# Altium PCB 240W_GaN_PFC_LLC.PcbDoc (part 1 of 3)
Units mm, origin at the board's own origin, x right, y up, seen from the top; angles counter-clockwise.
Board outline 120 x 71.8 mm, 4 copper layers (Top Layer, Layer 1, Layer 2, Bottom Layer), stack 1.787 mm thick; 163 components, 87 nets, 528 pads, 288 vias.
Unrouted connection lines stored in the file: 3.
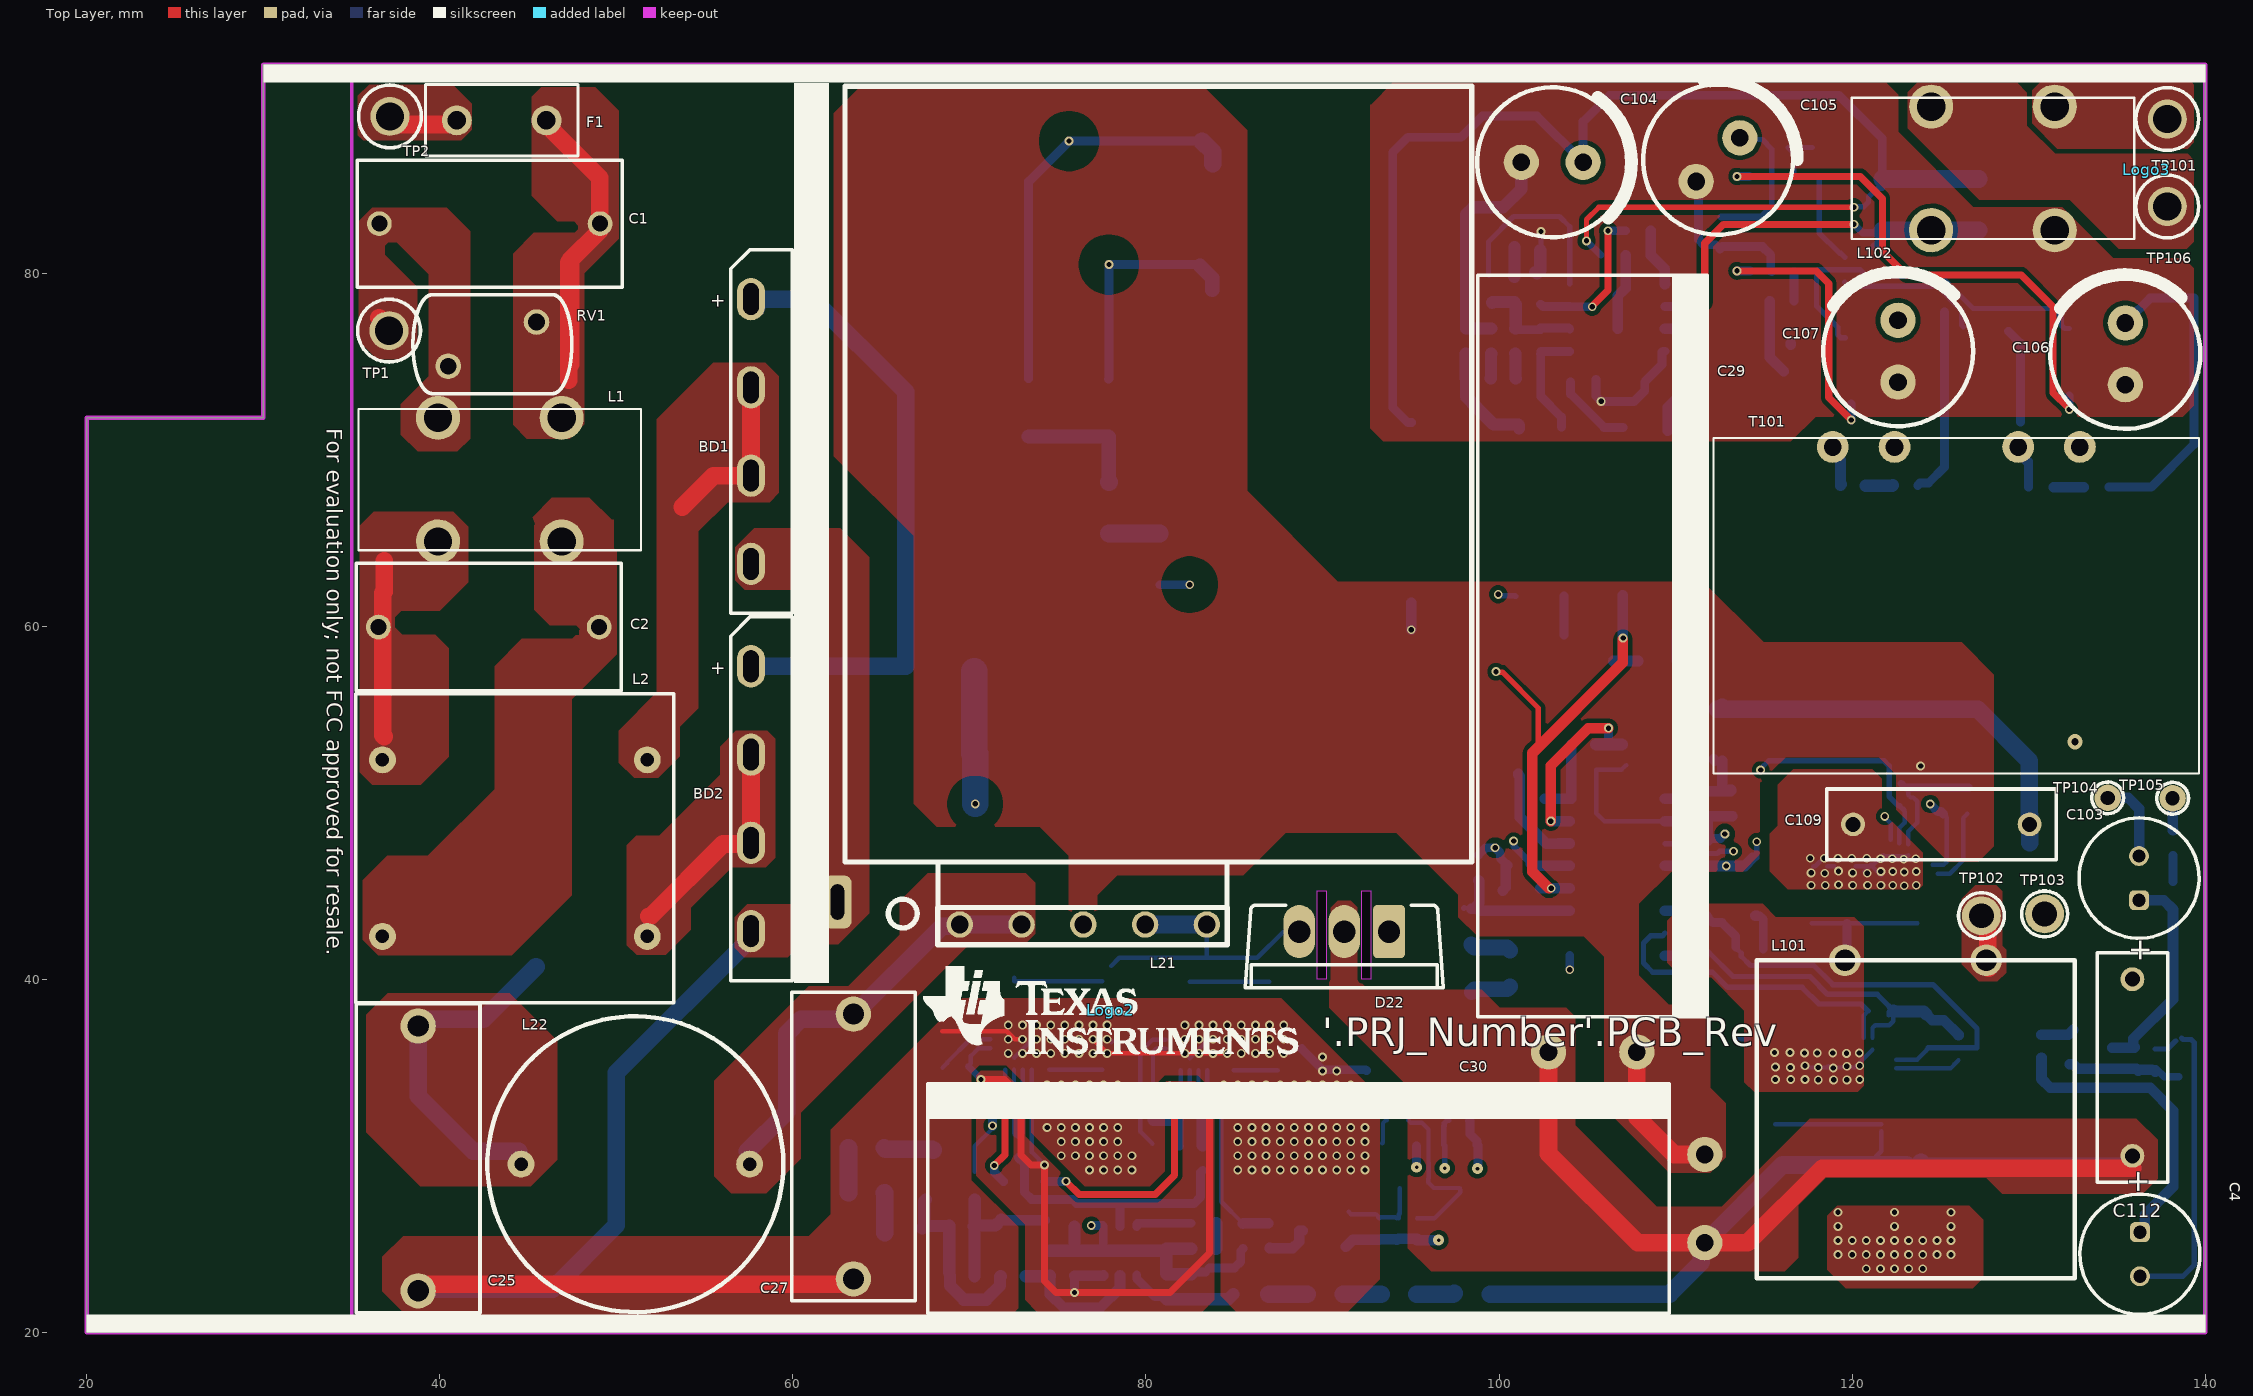
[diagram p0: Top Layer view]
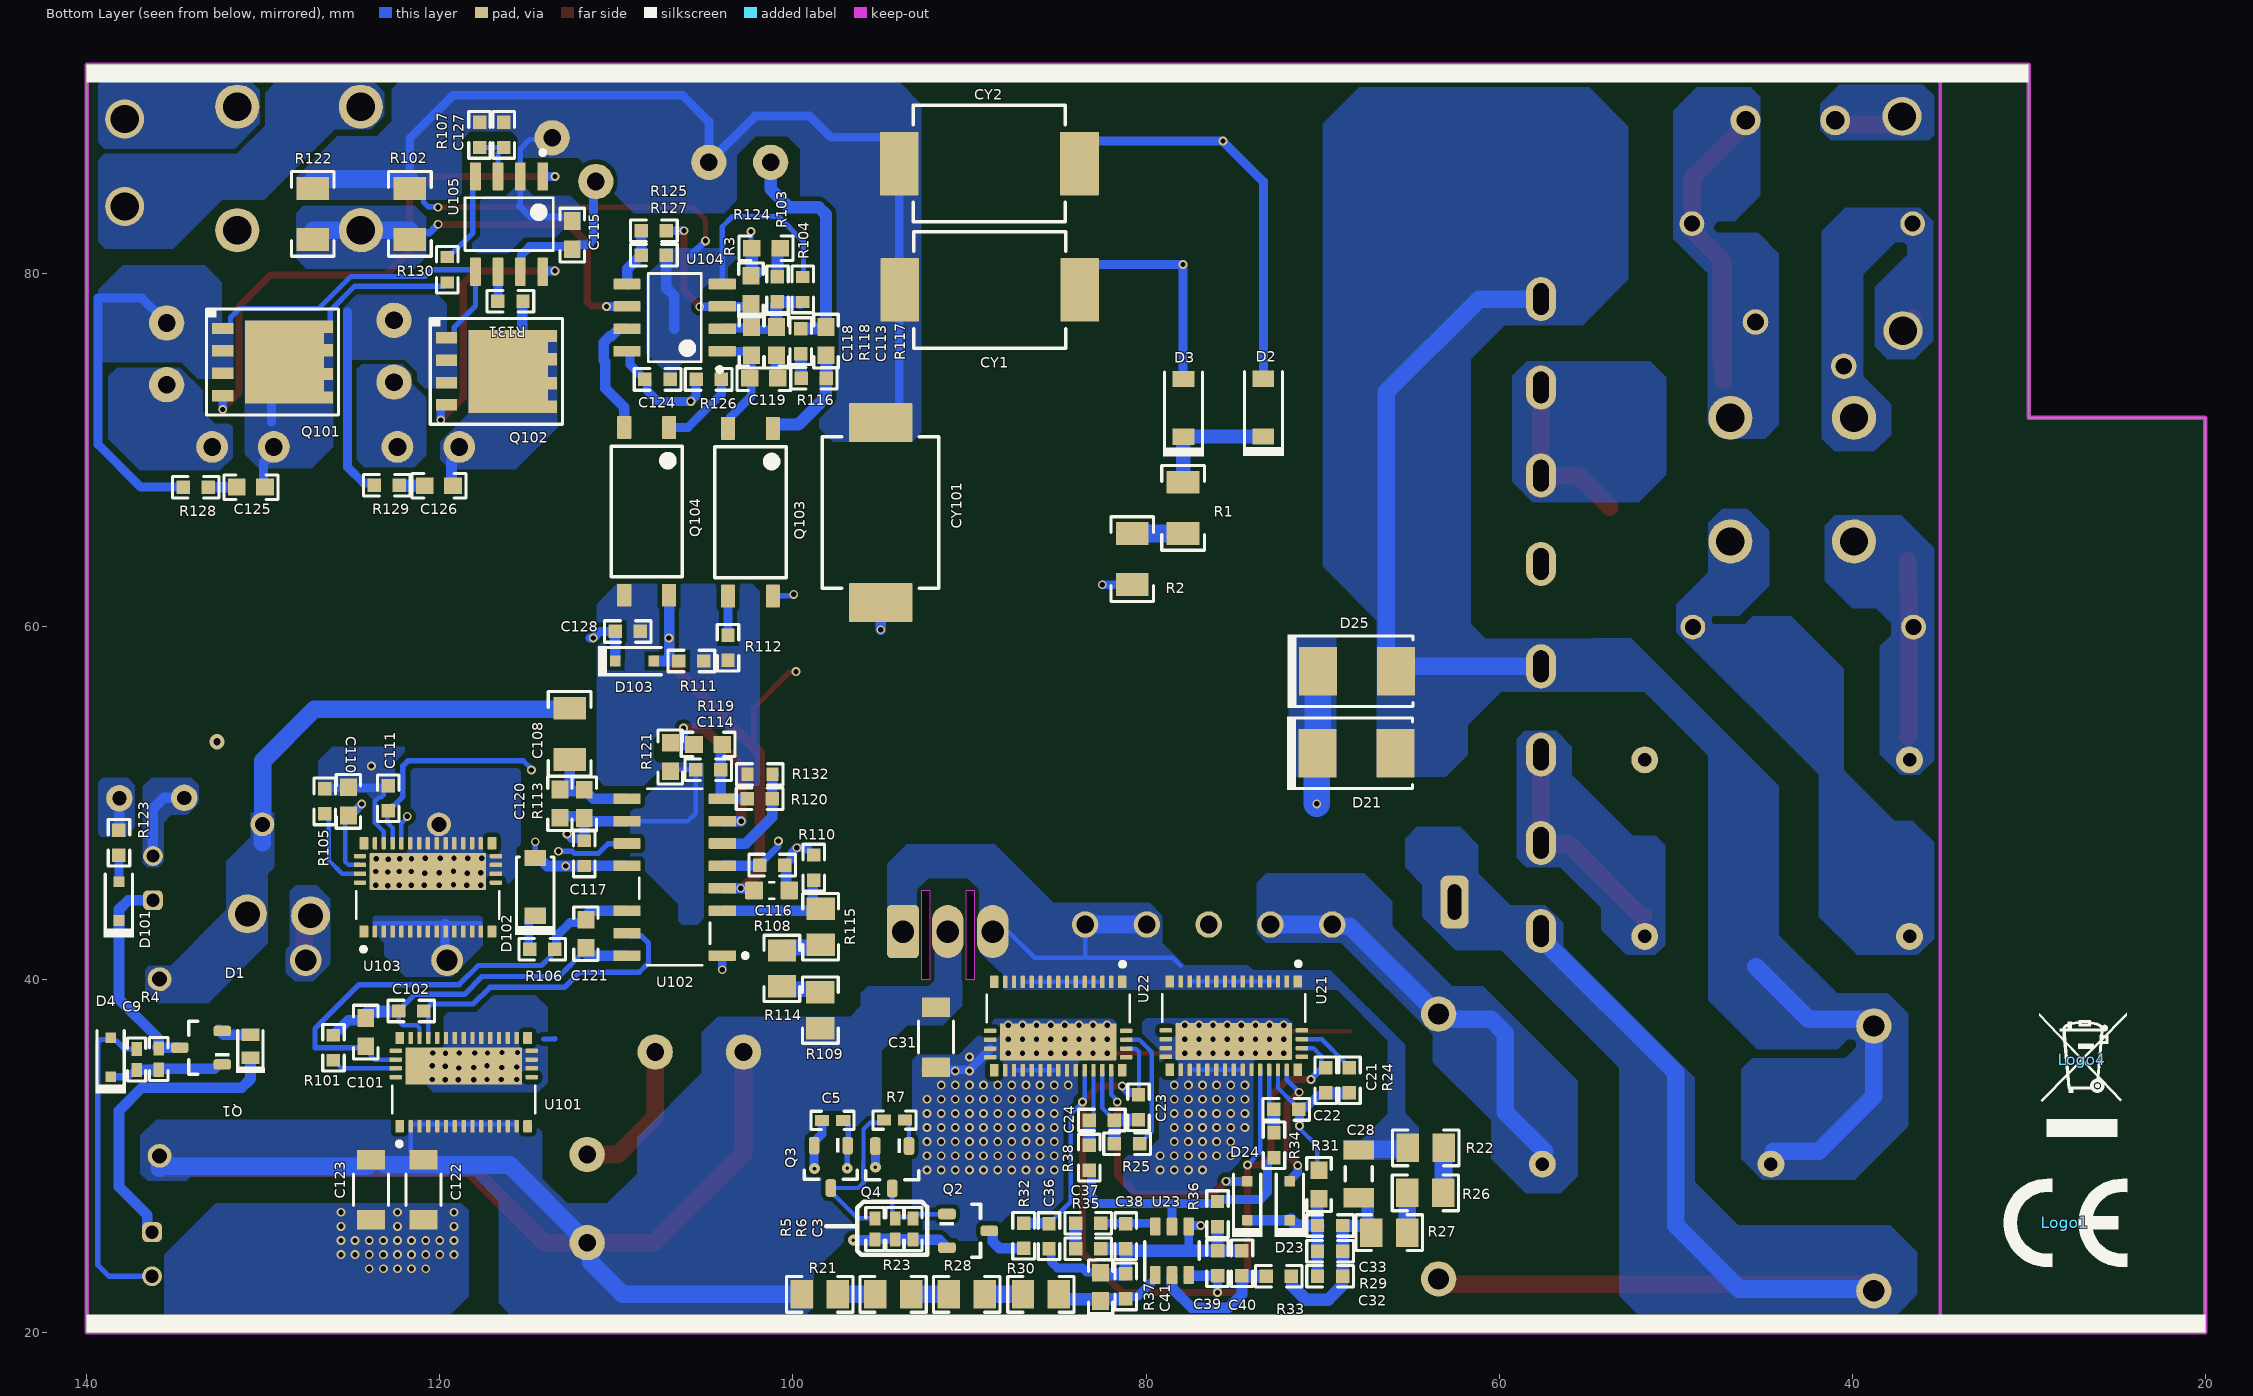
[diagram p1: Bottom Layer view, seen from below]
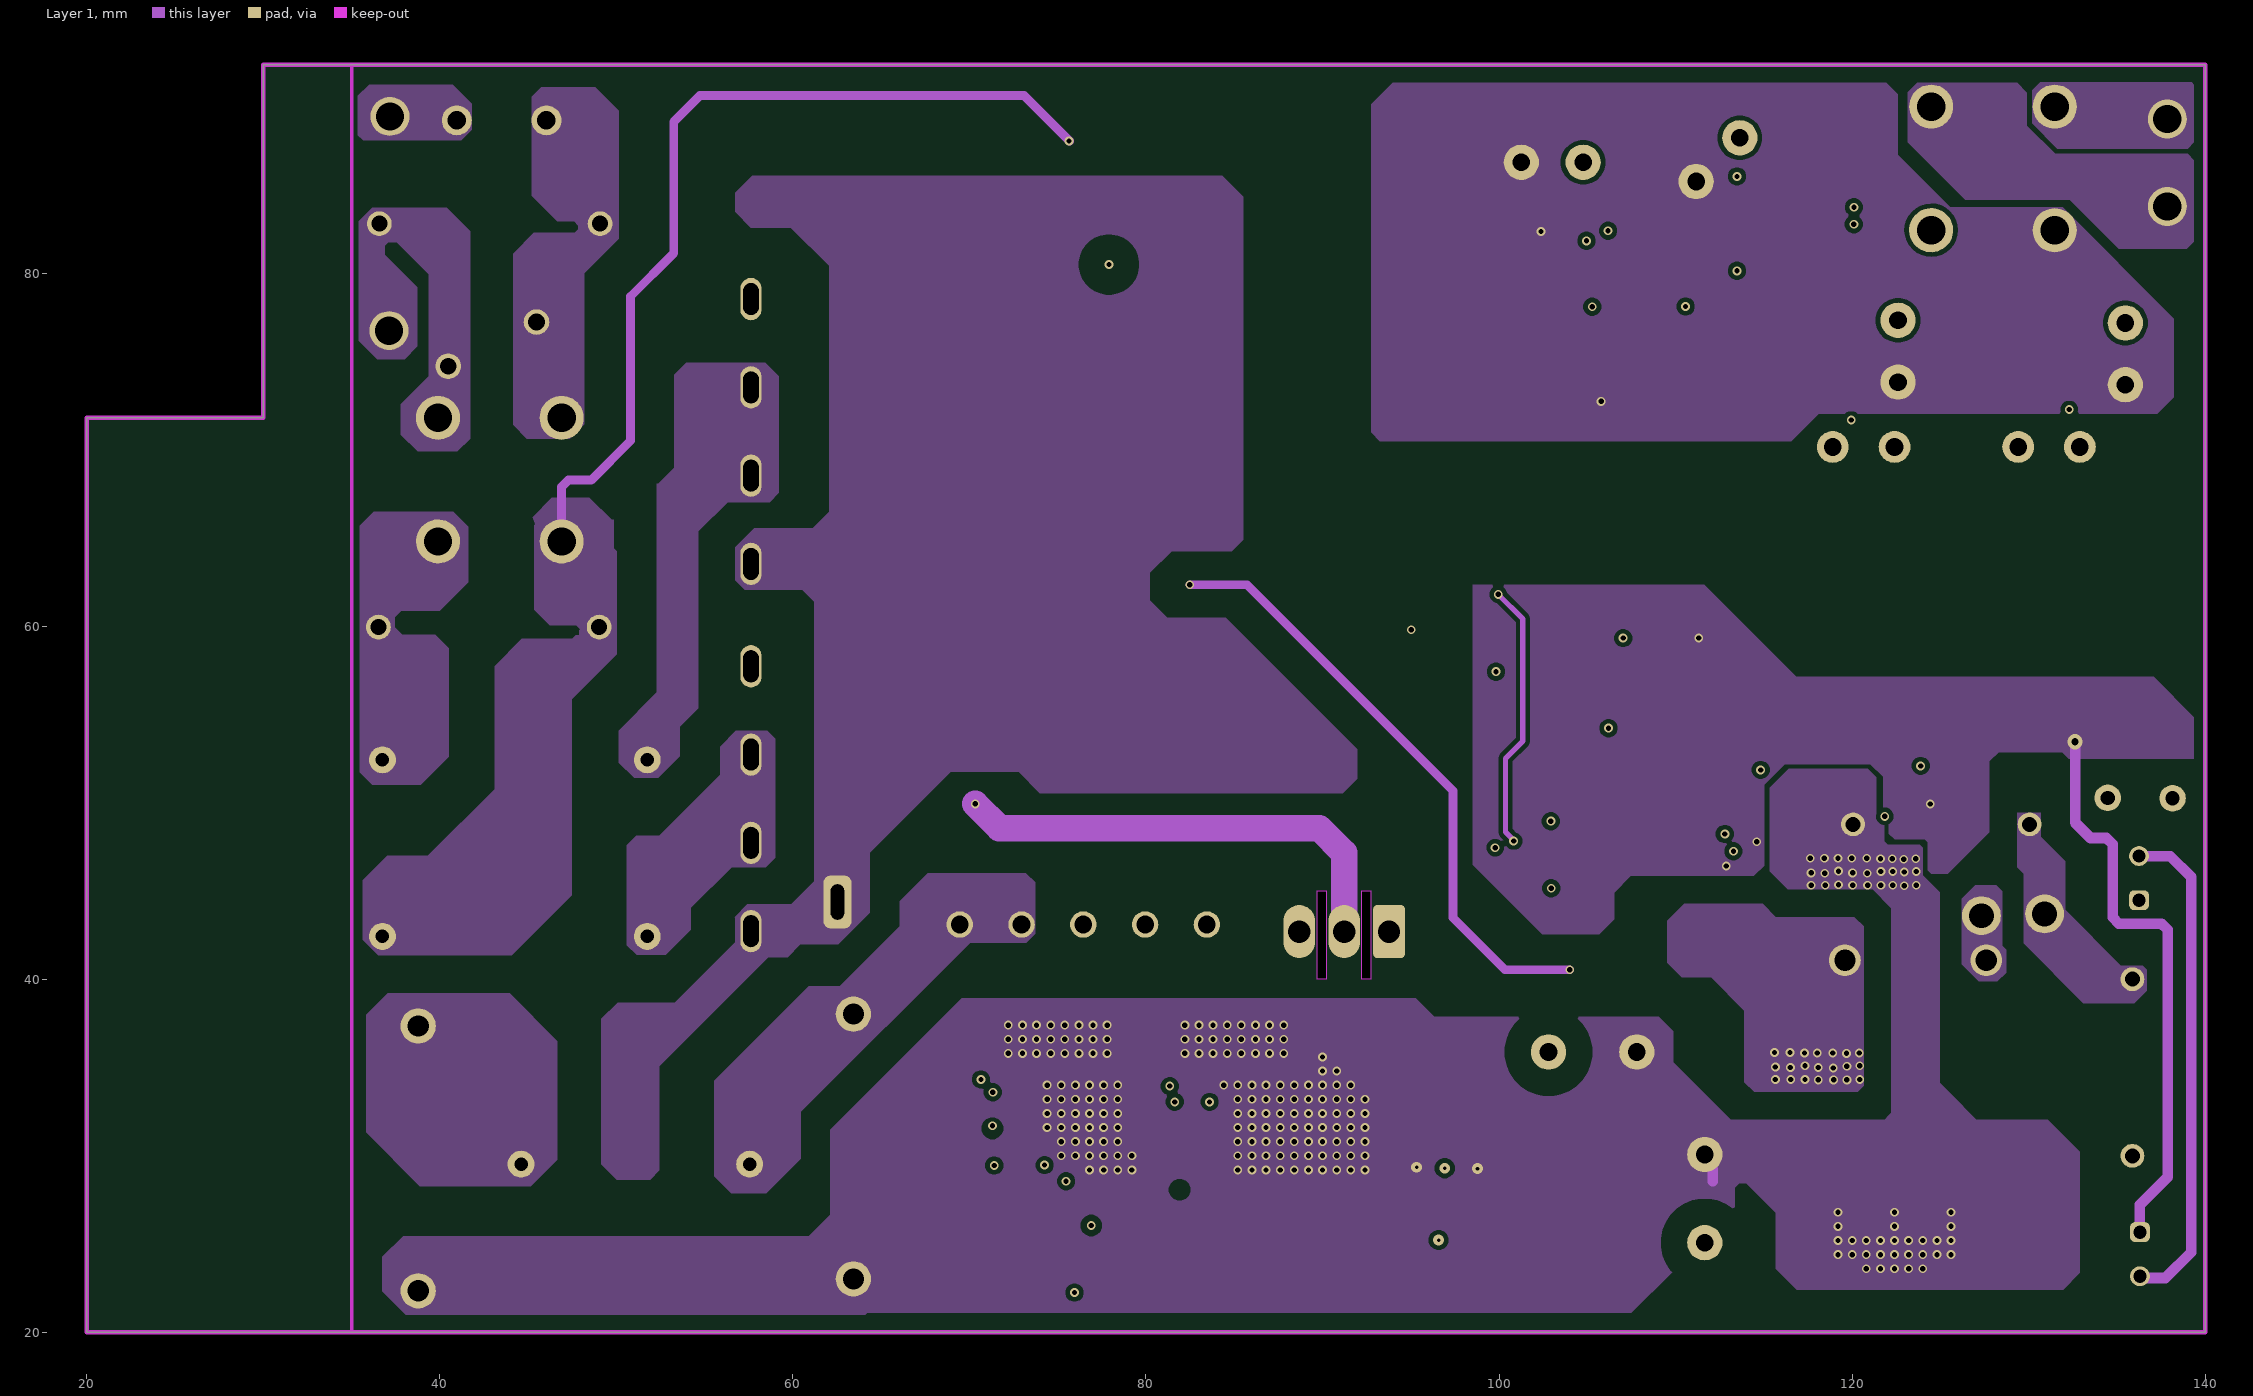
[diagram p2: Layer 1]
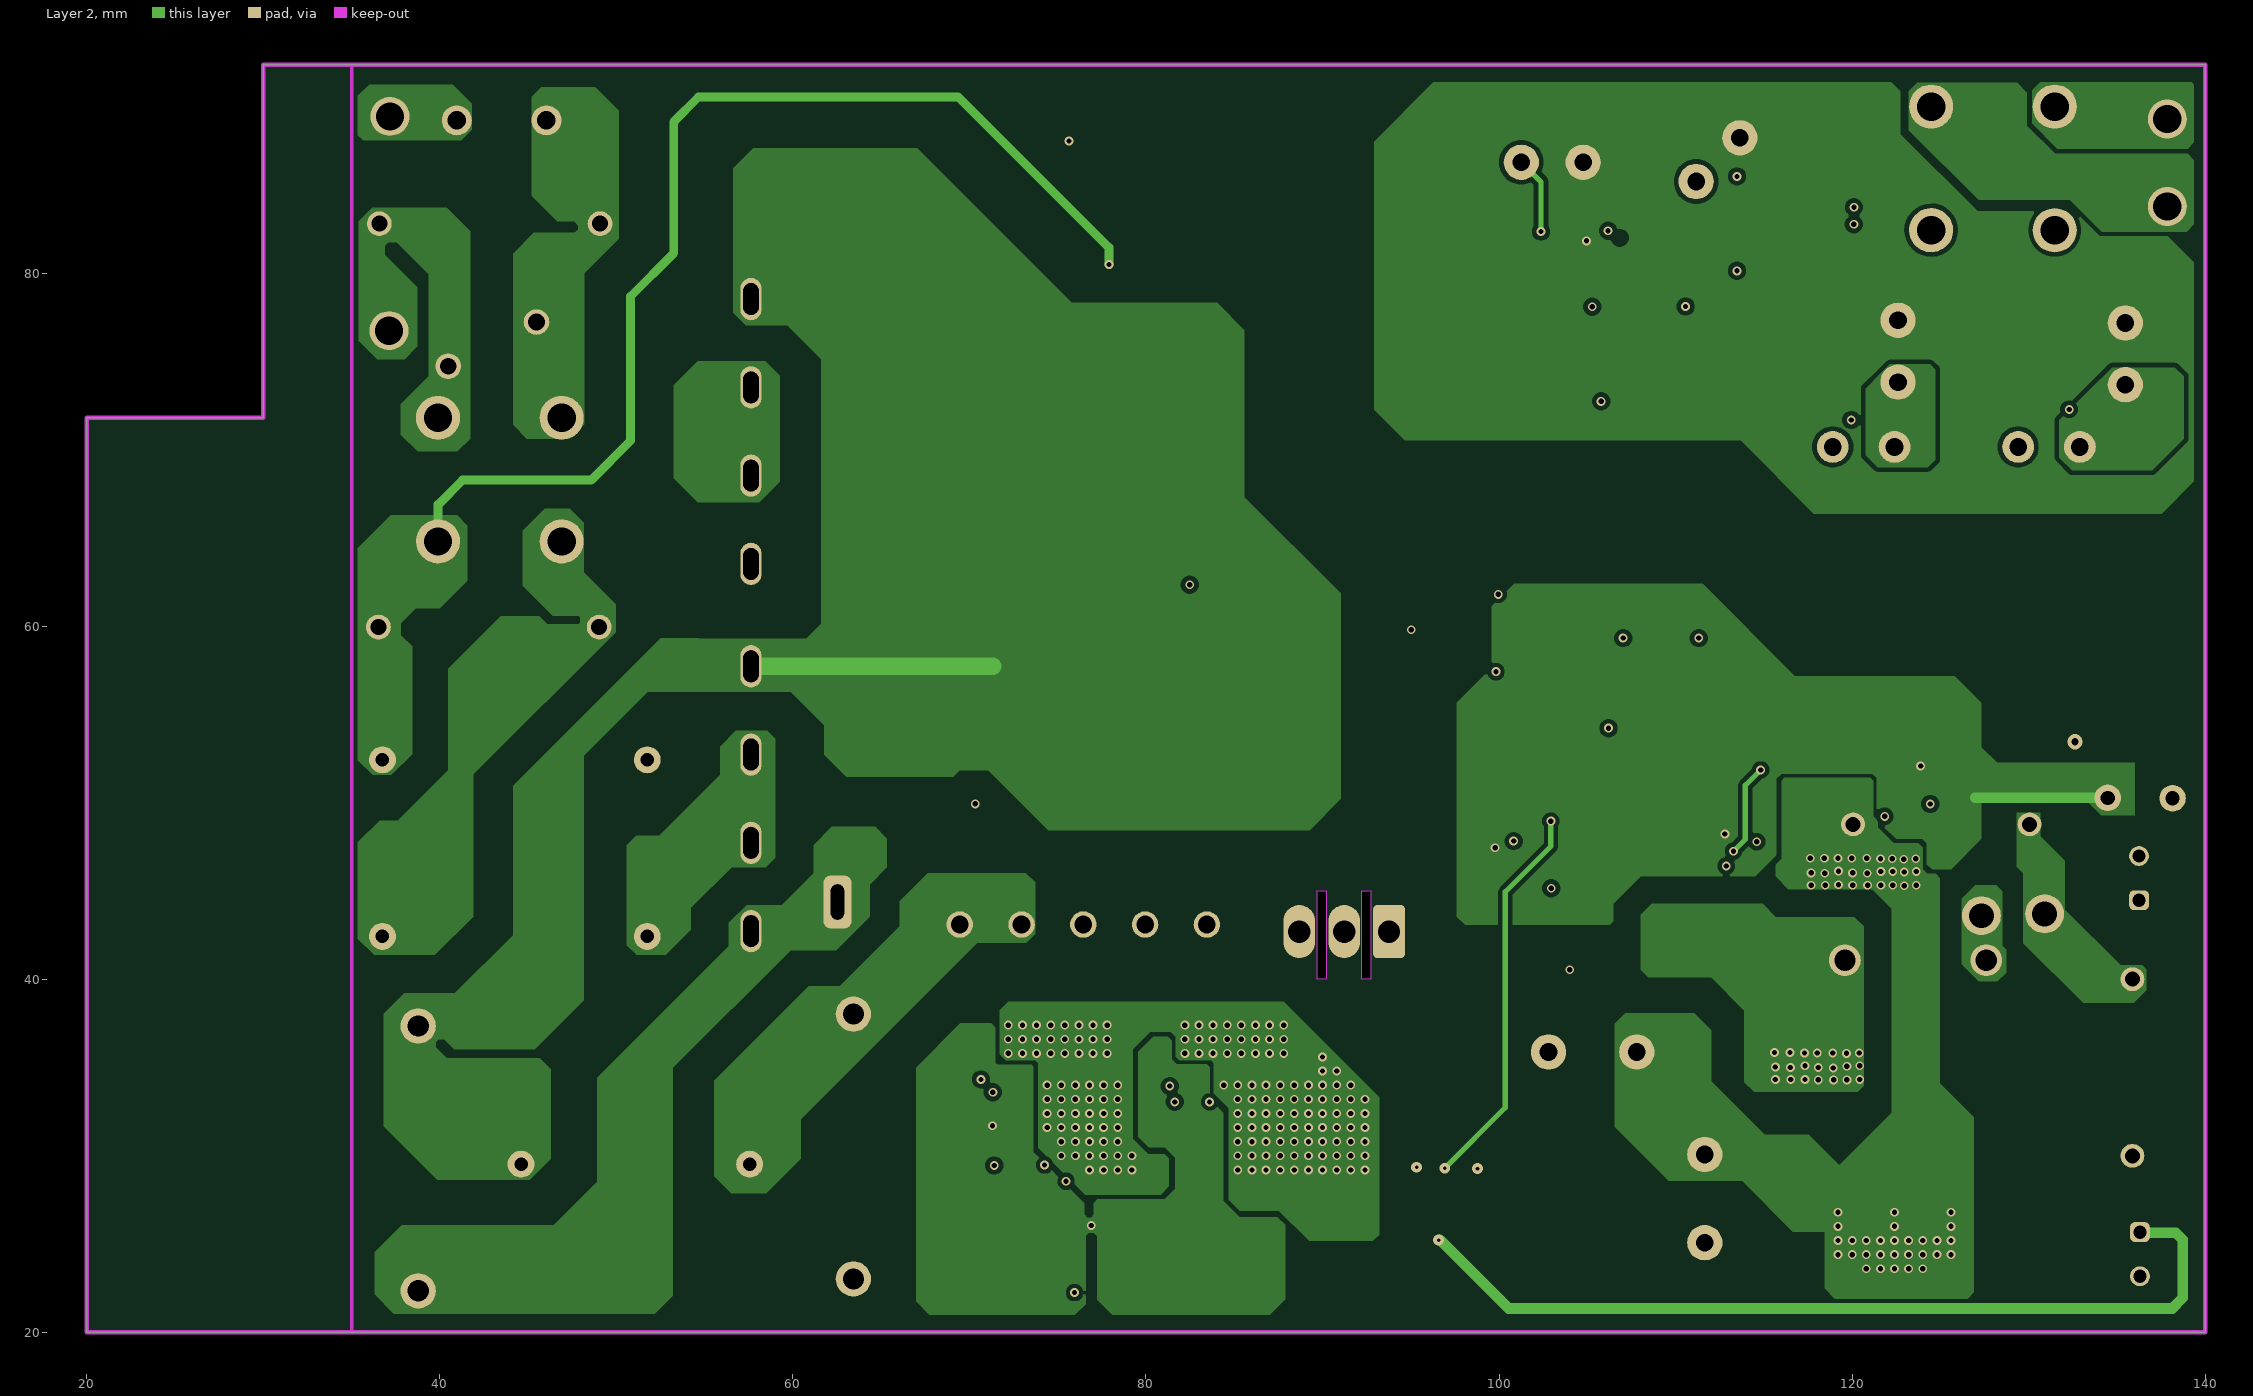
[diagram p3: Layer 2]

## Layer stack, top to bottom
Top Solder: solder mask 0.0102, Solder Resist, Dk 3.5
Top Layer: signal copper 0.0356
Dielectric 1: prepreg 0.0711, PP-006, Dk 4.1
Layer 1: signal copper 0.035
Dielectric1: core 1.5037, FR-4 High Tg, Dk 4.8
Layer 2: signal copper 0.035
Dielectric 2: prepreg 0.0711, PP-006, Dk 4.1
Bottom Layer: signal copper 0.0356
Bottom Solder: solder mask 0.0102, Solder Resist, Dk 3.5

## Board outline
20,20 20,71.8 30,71.8 30,91.8 140,91.8 140,20
cut-out: 89.7,40 89.7,45 90.2,45 90.2,40
cut-out: 92.225,40 92.225,45 92.725,45 92.725,40

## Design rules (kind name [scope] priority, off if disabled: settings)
AcuteAngle [All] p1: minimum=4.50000000000000E+0001 checktracksonly=FALSE
AssemblyTestPointUsage [All] p1: valid=2
BoardOutlineClearance BoardOutlineClearance_MountingHoles [OnCopper and InComponentClass('Mounting Holes')] p1: gap=1 ignorepadtopadclearanceinfootprint=FALSE
BoardOutlineClearance BoardOutlineClearance_Poly [OnCopper and IsPoly] p2: gap=0.635 ignorepadtopadclearanceinfootprint=FALSE
BoardOutlineClearance [OnCopper and Not InComponentClass('Logo') and not InComponentClass('FiducialMark') and not InRegion(1000,500,4000,800) and not InPoly] p3: gap=1.016 ignorepadtopadclearanceinfootprint=FALSE
Clearance Clearance_Keepouts [((IsTrack Or IsArc) And Not InPoly) And IsFree and IsKeepOut vs ((IsTrack Or IsArc) And Not InPoly) And IsFree and IsKeepOut] p1: gap=0 ignorepadtopadclearanceinfootprint=FALSE
Clearance Clearance_Poly [InPolygon] p2: gap=0.254 ignorepadtopadclearanceinfootprint=TRUE
Clearance Clearance_FiducialMark [IsKeepOut and InComponentClass('FiducialMark') vs IsPad and InComponentClass('FiducialMark')] p3: gap=0 ignorepadtopadclearanceinfootprint=FALSE
Clearance [All] p4: gap=0.25 ignorepadtopadclearanceinfootprint=TRUE
ComponentClearance ComponentClearance_MountingHoles_FiducialMarks [InComponentClass('Mounting Holes') vs InComponentClass('FiducialMark')] p1: gap=1.27 collisioncheckmode=3 verticalgap=0.254 showdistances=FALSE
ComponentClearance ComponentClearance_Shunt [InComponentClass('Header') vs InComponentClass('Shunt')] p2: gap=0 collisioncheckmode=3 verticalgap=0 showdistances=FALSE
ComponentClearance ComponentClearance_Logo [InComponentClass('Logo')] p3: gap=0.762 collisioncheckmode=3 verticalgap=0.254 showdistances=FALSE
ComponentClearance ComponentClearance_ScrewToNut [(HasFootprint('NY PMS 440 0025 PH')) vs (HasFootprint('Keystone_1902C'))] p4: gap=0.127 collisioncheckmode=3 verticalgap=0.254 showdistances=FALSE
ComponentClearance ComponentClearance_MountingHoles [InComponentClass('Mounting Holes')] p5: gap=2.54 collisioncheckmode=3 verticalgap=2540 showdistances=FALSE
ComponentClearance ComponentClearance_SmallPassives [HasFootprint('0201*') or HasFootprint('0402*') or HasFootprint('0508') or HasFootprint('0603*') or HasFootprint('0612') or HasFootprint('0805*') or HasFootprint('0815*') or HasFootprint('0830*') or HasFootprint('1206*') or HasFootprint('1210*') or HasFootprint('1808*') or HasFootprint('1812*') or HasFootprint('1825*') or HasFootprint('2010*') or HasFootprint('2220*') or HasFootprint('2225*') or HasFootprint('2512*') or HasFootprint('2728*') or HasFootprint('3518*') vs HasFootprint('0201*') or HasFootprint('0402*') or HasFootprint('0508') or HasFootprint('0603*') or HasFootprint('0612') or HasFootprint('0805*') or HasFootprint('0815*') or HasFootprint('0830*') or HasFootprint('1206*') or HasFootprint('1210*') or HasFootprint('1808*') or HasFootprint('1812*') or HasFootprint('1825*') or HasFootprint('2010*') or HasFootprint('2220*') or HasFootprint('2225*') or HasFootprint('2512*') or HasFootprint('2728*') or HasFootprint('3518*')] p6: gap=0.38 collisioncheckmode=3 verticalgap=0.254 showdistances=FALSE
ComponentClearance ComponentClearance_THtoSMT [IsThruComponent vs IsSMTComponent] p7: gap=0.762 collisioncheckmode=3 verticalgap=0.762 showdistances=FALSE
ComponentClearance ComponentClearance_THtoTH [IsThruComponent vs IsThruComponent] p8: gap=0.508 collisioncheckmode=3 verticalgap=0.762 showdistances=FALSE
ComponentClearance [All] p9: gap=0.508 collisioncheckmode=3 verticalgap=0.254 showdistances=FALSE
DiffPairsRouting [All] p1: maxlimit=2.54 minlimit=0.254 mostfreqgap=0.254 toplayer_minwidth=0.381 toplayer_maxwidth=0.381 toplayer_prefwidth=0.381 midlayer1_minwidth=0.381 midlayer1_maxwidth=0.381 midlayer1_prefwidth=0.381 midlayer2_minwidth=0.381 midlayer2_maxwidth=0.381 midlayer2_prefwidth=0.381 bottomlayer_minwidth=0.381 bottomlayer_maxwidth=0.381 bottomlayer_prefwidth=0.381 maxuncoupledlength=25.4
FabricationTestPointUsage TestPointUsage [All] p1: valid=2 allowmultiple=FALSE
FabricationTestpoint Testpoint [All] p1: side=3 testpointundercomponent=TRUE minsize=1.016 maxsize=2.54 preferedsize=1.524 minholesize=0 maxholesize=1.016 preferedholesize=0.813 testpointgrid=0.025 allowsidetop=TRUE allowsidebottom=TRUE usegrid=TRUE gridtolerance=0
FanoutControl Fanout_LCC [IsLCC] p1: bgadir=Out bgaviamode=Centered fanoutstyle=Auto fanoutdirection=Alternating viagrid=0.025 // Fanout_LCC (Default Rule)
FanoutControl Fanout_BGA [IsBGA] p2: bgadir=Out bgaviamode=Centered fanoutstyle=Auto fanoutdirection=Alternating viagrid=0.025 // Fanout_BGA (Default Rule)
FanoutControl Fanout_Default [All] p4: bgadir=Out bgaviamode=Centered fanoutstyle=Auto fanoutdirection=Alternating viagrid=0.025 // Fanout_Default (Default Rule)
FanoutControl Fanout_Small [(CompPinCount < 5)] p5: bgadir=Out bgaviamode=Centered fanoutstyle=Auto fanoutdirection=OutThenIn viagrid=0.025 // Fanout_Small (Default Rule)
HoleSize [All] p1: absolutevalues=TRUE maxlimit=6.375 minlimit=0.2 maxpercent=80.000 minpercent=20.000
MinimumAnnularRing MinimumAnnularRing_ThermalPadVias [IsVia and InAnyComponent] p1: minimumring=0.15
MinimumAnnularRing [All] p2: minimumring=0.2
MinimumSolderMaskSliver MinimumSolderMaskSliver_Logo [InComponentClass('Logo') vs InComponentClass('Logo')] p1: minsoldermaskwidth=0.018
MinimumSolderMaskSliver [All] p2: minsoldermaskwidth=0.1
PlaneConnect [All] p1: planeconnectstyle=Direct reliefexpansion=0.254 reliefentries=4 reliefconductorwidth=0.254 reliefairgap=0.254
PolygonConnect [All] p1: connectstyle=Direct reliefconductorwidth=0.254 reliefentries=4 polygonreliefangle="90 Angle" airgapwidth=0.254
RoutingVias ThermalPadVias [IsVia and InAnyComponent] p1: holewidth=0.2 width=0.5 viastyle="Through Hole" minholewidth=0.2 minwidth=0.5 maxholewidth=0.33 maxwidth=0.6
RoutingVias [All] p2: holewidth=0.406 width=0.864 viastyle="Through Hole" minholewidth=0.2 minwidth=0.61 maxholewidth=1.016 maxwidth=1.651
SilkToBoardRegionClearance [Not ((IsComment or IsDesignator) And (Hide <> 'False')) and not InRegion(1000,500,4000,800)] p1:
SilkToSilkClearance SilkToSilkClearance_Pb-FreeLogo [(HasFootprint('Pb-Free_Overlay_Medium') OR HasFootprint('Pb-Free_Overlay_Small')) vs (HasFootprint('Pb-Free_Overlay_Medium') OR HasFootprint('Pb-Free_Overlay_Small'))] p1: silktosilkclearance=0
SilkToSilkClearance [All] p2: silktosilkclearance=0.1
SilkToSolderMaskClearance SilkToComponentPadClearance [(IsPad or IsFill or IsRegion) and InAnycomponent] p1: minsilkscreentomaskgap=0.127 clearancetoexposedcopper=TRUE
SilkToSolderMaskClearance "Silk to Solder Mask Opening" [All] p2: minsilkscreentomaskgap=0.1 clearancetoexposedcopper=FALSE
SolderMaskExpansion [All] p1: expansion=0.05 istentingtop=FALSE
UnRoutedNet [All] p1: checkbadconnections=TRUE
Width [All] p1: maxlimit=2.54 minlimit=0.152 preferedwidth=0.254 checkconnectedcopper=TRUE
14 further rules are at their usual default settings.

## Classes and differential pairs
component class 240W_PFC_Stage: C3 C5 C21 C22 C23 C24 C25 C27 C28 C29 C30 C31 C32 C33 C36 C37 C38 C39 C40 C41 D21 D22 D23 D24 D25 L21 L22 Q2 Q3 Q4 R5 R6 R7 R21 R22 R23 R24 R25 R26 R27 R28 R29 R30 R31 R32 R33 R34 R35 R36 R37 R38 U21 U22 U23
component class 240W_LLC_Stage: C4 C9 C101 C102 C103 C104 C105 C106 C107 C108 C109 C110 C111 C112 C113 C114 C115 C116 C117 C118 C119 C120 C121 C122 C123 C124 C125 C126 C127 C128 CY101 D1 D4 D101 D102 D103 L101 L102 Q1 Q101 Q102 Q103 Q104 R3 R4 R101 R102 R103 R104 R105 R106 R107 R108 R109 R110 R111 R112 R113 R114 R115 R116 R117 R118 R119 R120 R121 R122 R123 R124 R125 R126 R127 R128 R129 R130 R131 R132 T101 TP101 TP102 TP103 TP104 TP105 TP106 U101 U102 U103 U104 U105
component class Logo: Logo2
component class 240W_GaN_PFC_LLC_AC_EMI: BD1 BD2 C1 C2 CY1 CY2 D2 D3 F1 L1 L2 Logo1 Logo2 Logo3 Logo4 R1 R2 RV1 TP1 TP2

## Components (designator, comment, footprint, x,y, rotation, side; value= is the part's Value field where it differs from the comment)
BD1 "GBL610" GBL610 60.025,71.027 r270 top locked
BD2 "GBL610" GBL610 60.025,50.225 r270 top locked
C1 "890324024002" WCAP-FTX2_1500x700x1250 42.825,82.8 r0 top locked value=0.22uF
C2 "890324024002" WCAP-FTX2_1500x700x1250 42.775,59.95 r0 top locked value=0.22uF
C3 "GRM155R61E104KA87D" 0402 93.2,25.85 r90 bottom value=0.1uF
C4 "35ZLJ100M6.3X11" Rubycon_630x1100 136.3,24.425 r270 top value=100uF
C5 "GRM155R61E104KA87D" 0402 97.75,32 r0 bottom value=0.1uF
C9 "CGA2B3X7R1E104K050BB" 0402 137.175,35.45 r90 bottom value=0.1uF
C21 "GRJ188R71E105KE11D" 0603_HV#1 69.825,34.275 r90 bottom value=1uF
C22 "CGA3E2C0G1H220J080AA" 0603_HV#1 72.05,32.625 r180 bottom value=22pF
C23 "GRJ188R71E105KE11D" 0603_HV#1 80.425,32.75 r90 bottom value=1uF
C24 "CGA3E2C0G1H220J080AA" 0603_HV#1 82.5,32.025 r180 bottom value=22pF
C25 "1uF/450V" C_film_17.5x7 38.775,29.85 r270 top locked
C27 "1uF/450V" C_film_17.5x7 63.425,30.525 r270 top locked
C28 "VJ1206A100JXGAT5Z" 1206L 67.95,28.975 r270 bottom value=10pF
C29 "82uF" Cap_12.5x40_H1 105.3,35.875 r90 top locked
C30 "82uF" Cap_12.5x40_H1 111.65,27.575 r180 top locked
C31 "C3216X7T2W104K160AE" 1206_180 91.9,36.725 r270 bottom value=0.1uF
C32 "GRM1885C1H332JA01D" 0603_HV#1 69.575,23.175 r0 bottom value=3300pF
C33 "GRM1885C1H221JA01D" 0603_HV#1 69.575,26.05 r0 bottom value=220pF
C36 "GCM188R71H224KA64D" 0603_HV#1 85.495,25.45 r270 bottom value=0.22uF
C37 "06033C105KAT2A" 0603_HV#1 83.275,26.175 r0 bottom value=1uF
C38 "GRM188R71H333KA61D" 0603_HV#1 81.15,25.45 r270 bottom value=0.033uF
C39 "06033C105KAT2A" 0603_HV#1 75.948,23.913 r90 bottom value=1uF
C40 "C0603C391J5GACTU" 0603_HV#1 74.564,23.906 r90 bottom value=390pF
C41 "C0603C222K5RACTU" 0603_HV#1 81.15,22.6 r90 bottom value=2200pF
C101 "06035C104KAZ2A" 0603 124.2,37 r90 bottom value=0.1uF
C102 "CGA3E2C0G1H220J080AA" 0603_HV#1 121.614,38.2 r0 bottom value=22pF
C103 "PHE426MA5150JR05" PHE426_1300x400x900 135.875,35 r90 top value=0.015uF
C104 "220uF" Cap_8_P3.5_V 103.01,86.275 r90 top locked
C105 "220uF" Cap_8_P3.5_V 112.4,86.425 r135 top locked
C106 "220uF" Cap_8_P3.5_V 135.475,75.425 r180 top locked
C107 "220uF" Cap_8_P3.5_V 122.6,75.575 r180 top locked
C108 "GRM31A5C2J151JW01D" 1206 112.65,53.9 r270 bottom value=150pF
C109 "PHE426MA5150JR05" PHE426_1300x400x900 125.05,48.775 r180 top value=0.015uF
C110 "06035C104KAZ2A" 0603 125.175,50.075 r90 bottom value=0.1uF
C111 "CGA3E2C0G1H220J080AA" 0603_HV#1 122.925,50.25 r90 bottom value=22pF
C112 "35ZLJ100M6.3X11" Rubycon_630x1100 136.25,45.725 r90 top value=100uF
C113 "C0603C472K5RACTU" 0603_HV#1 99.55,76.145 r270 bottom value=4700pF
C114 "GRM188Z71A475ME15D" 0603_HV#1 104.8,51.874 r0 bottom value=4.7uF
C115 "C1608X7R1V105K080AC" 0603 112.5,82.15 r90 bottom value=1uF
C116 "C0603C332F5GACTU" 0603_HV#1 101.175,46.467 r180 bottom value=3300pF
C117 "GRJ188R71E105KE11D" 0603_HV#2 111.825,47.125 r270 bottom value=1uF
C118 "GRM1885C1H181JA01D" 0603 102.35,76.145 r270 bottom value=180pF
C119 "C1608X7R1H473K080AA" 0603 101.65,74.045 r0 bottom value=0.047uF
C120 "C0603C561K5RACTU" 0603 113.2,49.95 r270 bottom value=560pF
C121 "C0603C101F5GACTU" 0603 111.725,42.575 r90 bottom value=100pF
C122 "C1206C223KDRACTU" 1206_190 120.925,28.075 r270 bottom value=0.022uF
C123 "C1206C223KDRACTU" 1206_190 123.9,28.075 r270 bottom value=0.022uF
C124 "C0603C104K5RACTU" 0603_HV#1 107.67,73.975 r180 bottom value=0.1uF
C125 "C1608C0G2A101F080AA" 0603 130.7,67.875 r180 bottom value=100pF
C126 "C1608C0G2A101F080AA" 0603 120.05,67.95 r180 bottom value=100pF
C127 "C0603X102K5RACTU" 0603_HV#1 116.375,87.825 r270 bottom value=1000pF
C128 "GRJ188R71E105KE11D" 0603_HV#1 109.35,59.7 r0 bottom value=1uF
CY1 "DK1E3EA102M86RAH01" DK1_86 88.85,79.05 r0 bottom value=1000pF
CY2 "DK1E3EA102M86RAH01" DK1_86 88.875,86.2 r0 bottom value=1000pF
CY101 "DK1E3EA102M86RAH01" DK1_86 95.035,66.436 r270 bottom value=1000pF
D1 "CD0603-B0130L" Diode_0603 130.725,36.2 r90 bottom value=35V
D2 "S1MFL" SOD-123 73.35,72.375 r90 bottom value=1000V
D3 "S1MFL" SOD-123 77.875,72.362 r90 bottom value=1000V
D4 "MMSZ5242BS-7-F" SOD-323 138.65,35.575 r90 bottom value=12V
D21 "S3MB-13-F" SMB 68.075,52.8 r180 bottom value=1000V
D22 "MUR1660CTG" TO-220AB 91.225,42.7 r180 top locked value=600V
D23 "1N4148WS-7-F" SOD-323 71.85,27.45 r90 bottom value=75V
D24 "1N4148WS-7-F" SOD-323 74.275,27.45 r90 bottom value=75V
D25 "S3MB-13-F" SMB 68.05,57.45 r180 bottom value=1000V
D101 "SD103AWS-TP" SOD-323 138.175,44.425 r90 bottom value=40V
D102 "UFM15PL-TP" SOD-123FL 114.6,45.237 r90 bottom value=600V
D103 "MM3Z18VST1G" SOD-323 108.975,58.025 r180 bottom value=18V
F1 "39213150000" FUSE_392 43.5,88.65 r180 top locked
L1 "T10x6x5" T10x6x5 43.425,68.275 r90 top locked
L2 "DCN181713H-222HF" CM_DCN181713H 44.25,47.425 r90 top locked
L21 "LPFC" EQ33 80.7,68.6 r180 top locked
L22 "050AT7502HM" L_Ring_H_D=16.76mm 51.075,29.525 r0 top locked
L101 "30uH" ATQ18 123.595,41.075 r0 top
L102 "T10x6x5" T10x6x5 128,85.902 r90 top locked
Logo1 "CE Mark" CE_Mark_5mm 27.925,26.2 r180 bottom
Logo2 "Texas Instruments" TI_Stacked_Overlay_Small 78,38.25 r0 top
Logo3 "FCC disclaimer" FCC_disclaimer 136.69,85.852 r0 top
Logo4 "WEEE logo" WEEE_Minimum 26.975,35.45 r180 bottom
Q1 "MMBT3904-7-F" SOT-23 133.525,36.125 r0 bottom value="40 V"
Q2 "SI2309CDS-T1-E3" SOT-23 90.075,25.75 r180 bottom value=-60V
Q3 "2N7002-7-F" SOT-23 97.85,29.375 r270 bottom value=60V
Q4 "2N7002-7-F" SOT-23 94.375,29.35 r270 bottom value=60V
Q101 "BSC040N08NS5ATMA1" PG-TDSON-8 129.475,74.955 r180 bottom value=30V
Q102 "BSC040N08NS5ATMA1" PG-TDSON-8 116.8,74.435 r180 bottom value=30V
Q103 "TLP383(GR-TPL,E" FP-TLP383(GR-TPL,E_SO6-4-MFG 102.408,66.45 r270 bottom
Q104 "TLP383(GR-TPL,E" FP-TLP383(GR-TPL,E_SO6-4-MFG 108.283,66.5 r270 bottom
R1 "CRCW12062K20JNEA" 1206 77.9,66.7 r90 bottom value=2.2k
R2 "CRCW12062K20JNEA" 1206 80.775,63.8 r90 bottom value=2.2k
R3 "RC0603JR-070RL" 0603 101.525,81.4 r0 bottom value=0
R4 "CRG0402F4K7" 0402 135.925,35.475 r90 bottom value=4.70k
R5 "CRCW0402499KFKED" 0402 95.35,25.85 r270 bottom value=499k
R6 "CRCW0402499KFKED" 0402 94.2,25.85 r270 bottom value=499k
R7 "CRCW0402499KFKED" 0402 94.25,32.025 r0 bottom value=499k
R21 "CRCW08052M74FKEA" 0805_HV 98.475,22.15 r0 bottom value=2.74Meg
R22 "CRCW08053M24FKEA" 0805_HV 64.15,30.45 r0 bottom value=3.24Meg
R23 "CRCW08052M74FKEA" 0805_HV 94.325,22.15 r0 bottom value=2.74Meg
R24 "CRCW0603150KJNEA" 0603_HV#1 68.475,34.275 r90 bottom value=150k
R25 "CRCW0603150KJNEA" 0603_HV#1 81.075,30.675 r180 bottom value=150k
R26 "CRCW08053M24FKEA" 0805_HV 64.175,27.9 r180 bottom value=3.24Meg
R27 "CRCW08053M24FKEA" 0805_HV 66.225,25.647 r180 bottom value=3.24Meg
R28 "CRCW08052M74FKEA" 0805_HV 90.15,22.15 r0 bottom value=2.74Meg
R29 "RC0603FR-0724K3L" 0603_HV#1 69.575,24.6 r180 bottom value=24.3k
R30 "CRCW08051M82FKEA" 0805_HV 85.95,22.15 r0 bottom value=1.82Meg
R31 "RC0603FR-0764R9L" 0603 70.2,28.375 r270 bottom value=64.9
R32 "CRCW060320R0JNEA" 0603_HV#1 86.935,25.464 r270 bottom value=20
R33 "RC0603JR-07750RL" 0603_HV#1 72.475,23.175 r180 bottom value=750
R34 "CRCW060347R0JNEA" 0603_HV#1 72.75,30.6 r90 bottom value=47
R35 "CRCW0603180KJNEA" 0603_HV#1 83.275,24.725 r0 bottom value=180k
R36 "CRCW0603220KJNEA" 0603_HV#1 75.95,26.7 r90 bottom value=220k
R37 "RC0603FR-0766K5L" 0603 82.575,22.575 r270 bottom value=66.5k
R38 "CRCW060347R0JNEA" 0603_HV#1 83.211,29.895 r270 bottom value=47
R101 "CRCW0603150KJNEA" 0603_HV#2 126.025,36.125 r270 bottom value=150k
R102 "CSNL1206FT3L00" 1206 121.7,83.35 r270 bottom value=0.003
R103 "RC0603FR-07220KL" 0603_HV#1 100.875,79.075 r90 bottom value=220k
R104 "RC0603FR-0725K5L" 0603_HV#3 99.45,79.075 r270 bottom value=25.5k
R105 "CRCW0603150KJNEA" 0603_HV#1 126.525,50.075 r270 bottom value=150k
R106 "RC0603FR-071RL" 0603_HV#1 114.2,41.7 r180 bottom value=1.00
R107 "RC0603FR-0721K5L" 0603_HV#1 117.75,87.825 r270 bottom value=21.5k
R108 "B57371V2474J060" FP-B57371V2474J060_0603-MFG 101.2,45.025 r0 bottom value=470k
R109 "ERJ-6GEYJ335V" 0805_HV 98.45,38.25 r90 bottom value=3.3Meg
R110 "RC0603FR-0735K7L" 0603_HV#1 98.825,46.325 r270 bottom value=35.7k
R111 "RC0603FR-0714KL" 0603_HV#1 105.75,58.025 r0 bottom value=14.0k
R112 "RC0603JR-0710KL" 0603_HV#1 103.678,58.775 r90 bottom value=10k
R113 "CRCW0603143RFKEA" 0603 111.825,49.936 r90 bottom value=143
R114 "ERJ-6GEYJ335V" 0805_HV 100.625,40.611 r270 bottom value=3.3Meg
R115 "ERJ-6GEYJ335V" 0805_HV 98.425,42.975 r270 bottom value=3.3Meg
R116 "CRCW0603750RFKEA" 0603_HV#1 98.825,74.045 r0 bottom value=750
R117 "RC0603FR-0749K9L" 0603 98.125,76.145 r90 bottom value=49.9k
R118 "M55342K12B10E0T" 0603 100.925,76.145 r90 bottom value=10.0k
R119 "RC0603FR-0782KL" 0603 104.8,53.3 r180 bottom value=82.0k
R120 "RC0603FR-07649KL" 0603_HV#1 101.886,50.229 r0 bottom value=649k
R121 "RC0603FR-07360KL" 0603 106.94,52.586 r90 bottom value=360k
R122 "CSNL1206FT3L00" 1206 127.2,83.35 r270 bottom value=0.003
R123 "CRCW06034R70JNEA" 0603_HV#1 138.175,47.736 r90 bottom value=4.7
R124 "RC0603FR-075K49L" 0603 102.375,79.05 r90 bottom value=5.49k
R125 "RC0603FR-07221KL" 0603_HV#1 107.875,82.4 r180 bottom value=221k
R126 "CRCW06032K00JNEA" 0603_HV#1 104.776,73.975 r180 bottom value=2.0k
R127 "RC0603FR-071K47L" 0603_HV#1 107.875,81.02 r0 bottom value=1.47k
R128 "CRCW060312R0JNEA" 0603_HV#1 133.825,67.875 r0 bottom value=12
R129 "CRCW060312R0JNEA" 0603_HV#1 123,67.975 r0 bottom value=12
R130 "RC0603JR-07330RL" 0603_HV#3 119.575,80.189 r90 bottom value=330
R131 "RC0603JR-07330RL" 0603_HV#1 116,78.4 r0 bottom value=330
R132 "RC0603FR-07162KL" 0603_HV#3 101.875,51.6 r180 bottom value=162k
RV1 "V275LA2P" Littelfuse_V275LA_7MM 42.975,75.975 r180 top
T101 "ATQ27" ATQ27 125.848,70.622 r0 top locked
TP1 "N" Keystone5011#1 37.125,76.739 r0 top
TP2 "L" Keystone5011#1 37.175,88.875 r0 top locked
TP101 "OUT" Keystone5011#1 137.85,88.725 r0 top
TP102 "P1" Keystone5011#2 127.325,43.6 r0 top
TP103 "P2" Keystone5011#2 130.9,43.7 r0 top
TP104 "A2" Keystone5011#3 134.475,50.275 r0 top
TP105 "A1" Keystone5011#3 138.15,50.25 r0 top
TP106 "RTN" Keystone5011#1 137.849,83.773 r0 top
U21 "LMG3622REQ" REQ0038A-MFG 75.025,37.375 r270 bottom locked
U22 "LMG3622REQ" REQ0038A-MFG 84.975,37.348 r270 bottom locked
U23 "UCC28056ADBVR" DBV0006A_N 78.527,24.618 r90 bottom
U101 "LMG3614REQR" REQ0038A-MFG 118.65,34.175 r90 bottom
U102 "UCC256604DDBR" DDB0014A-MFG 106.7,45.784 r0 bottom
U103 "LMG3614REQR" REQ0038A-MFG 120.675,45.2 r90 bottom
U104 "TL103WBIDR" D0008A-MFG 106.7,77.475 r0 bottom
U105 "MP6924AGS-P" FP-MP6924AGS-P_SOIC8-MFG 116.075,82.775 r270 bottom locked

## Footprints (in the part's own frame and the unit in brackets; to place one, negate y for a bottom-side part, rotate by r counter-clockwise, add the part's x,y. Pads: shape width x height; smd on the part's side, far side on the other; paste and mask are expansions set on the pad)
0402 [mm] "0402 from SM-752 data"
  rect 0.8x0.6 smd: 1(-0.6,0) 2(0.6,0)
  silkscreen extent -1.22,-0.52 1.22,0.52, body extent -0.55,-0.3 0.55,0.3, height 0.6
0603 [mm] "0603 from SM-752 data"
  rect 1x0.95 smd: 1(-0.8,0) 2(0.8,0)
  silkscreen extent -1.52,-0.69 1.52,0.69, body extent -0.87,-0.47 0.87,0.47, height 1
0603_HV#1 [mil] "Ernesto recommended land pattern.  26 mil between pads."
  rect 30x30 smd: 1(-28,0) 2(28,0)
  silkscreen extent -52,-24 52,24, body extent -34,-19 34,19, height 39
0603_HV#2 [mil] "Ernesto recommended land pattern.  26 mil between pads."
  rect 27.56x30 smd: 1(-28,0) 2(28,0)
  silkscreen extent -52,-24 52,24, body extent -34,-19 34,19, height 39
0603_HV#3 [mil] "Ernesto recommended land pattern.  26 mil between pads."
  rect 26.77x30 smd: 1(-28,0) 2(28,0)
  silkscreen extent -52,-24 52,24, body extent -34,-19 34,19, height 39
0805_HV [mil] "0805 with 30mil clearance between pads"
  rect 50x63 smd: 1(-40,0) 2(40,0)
  silkscreen extent -74,-40 74,40, body extent -43,-29 43,29, height 57
1206 [mm] "1206 from SM-752 data"
  rect 1.3x1.85 smd: 1(-1.45,0) 2(1.45,0)
  silkscreen extent -2.4,-1.21 2.4,1.21, body extent -1.7,-0.9 1.7,0.9, height 1.35
1206_180 [mm] "1206_180"
  rect 1.1x1.6 smd: 1(-1.7,0) 2(1.7,0)
  silkscreen extent -0.9,-1 0.9,1, body extent -1.75,-0.95 1.75,0.95, height 1.8
1206_190 [mm] "1206_190"
  rect 1.1x1.6 smd: 1(-1.7,0) 2(1.7,0)
  silkscreen extent -0.9,-1 0.9,1, body extent -1.75,-0.95 1.75,0.95, height 1.9
1206L [mm] "1206 from SM-752 data"
  rect 1.1x1.75 smd: 1(-1.35,0) 2(1.35,0)
  silkscreen extent -0.4,-0.77 0.4,0.77, body extent -1.7,-0.9 1.7,0.9, height 1.35
ATQ18 [mm]
  round 1.8 hole 1.2: 1(-4.005,0) 4(4.005,0)
  round 1 on Top Overlay: 2(-1.335,0) 3(1.335,0)
  silkscreen extent -9,-18 9,0
ATQ27 [mm]
  round 1.8 hole 1: 1(-6.948,-0.472) 2(-3.448,-0.472) 4(3.552,-0.472) 5(7.052,-0.472)
  round 1 on Top Overlay: 3(0.052,-0.472)
  silkscreen extent -13.7,-18.97 13.8,0.03, body extent -13.7,-18.97 13.8,0.03, height 25
C_film_17.5x7 [mm] "Xcap_Film 17.5 x 7mm"
  round 2 hole 1.2: 1(-7.5,0) 2(7.5,0)
  silkscreen extent -8.75,-3.5 8.75,3.5
Cap_8_P3.5_V [mm]
  round 2 hole 1: 1(0,1.75) 2(0,-1.75)
  silkscreen extent -4.25,-4.5 4.25,4.25
Cap_12.5x40_H1 [mm]
  round 2 hole 1: 1(0,2.5) 2(0,-2.5)
  silkscreen extent 2,-6.5 44,6.5
CE_Mark_5mm [mm] "Minimum text height for CE Mark"
  silkscreen extent -3.5,-2.5 3.5,2.5
CM_DCN181713H [mil]
  round 60 hole 30: 1(-196.85,295.28) 2(196.85,295.28) 3(196.85,-295.28) 4(-196.85,-295.28)
  silkscreen extent -344,-354 344,354
D0008A-MFG [mm]
  rrect17% 1.55x0.6 smd paste+0 mask+0: 1(-2.7,1.905) 2(-2.7,0.635) 3(-2.7,-0.635) 4(-2.7,-1.905) 5(2.7,-1.905) 6(2.7,-0.635) 7(2.7,0.635) 8(2.7,1.905)
  silkscreen extent -2.67,-2.5 1.5,3.06, body extent -3,-2.45 3,2.45, height 1.75
DBV0006A_N [mm] "SOT23, 6-Leads, Body 2.9x1.6mm, Pitch 0.95mm, Lead Span 2.8mm, IPC Medium Density"
  rrect17% 1x0.6 smd: 1(-1.375,0.95) 2(-1.375,0) 3(-1.375,-0.95) 4(1.375,-0.95) 5(1.375,0) 6(1.375,0.95)
  silkscreen extent -1.68,-1.55 0.5,1.55, body extent -1.42,-1.46 1.42,1.46, height 1.12
DDB0014A-MFG [mm]
  rrect17% 1.55x0.6 smd paste+0 mask+0: 1(-2.7,4.445) 3(-2.7,1.905) 4(-2.7,0.635) 5(-2.7,-0.635) 6(-2.7,-1.905) 7(-2.7,-3.175) 8(-2.7,-4.445) 9(2.7,-4.445) 10(2.7,-3.175) 11(2.7,-1.905) 12(2.7,-0.635) 14(2.7,1.905) 15(2.7,3.175) 16(2.7,4.445)
  silkscreen extent -4.12,-5 2,5, body extent -3.01,-4.95 3.01,4.95, height 1.75
Diode_0603 [mm] "Based on Bourns recommended land pattern Rev 10/09"
  rect 0.7x1 smd: 1(-0.65,0) 2(0.65,0)
  silkscreen extent -1.5,-0.8 0.9,0.8, body extent -0.9,-0.5 0.9,0.5, height 0.85
DK1_86 [mm] "SMD, 2-Leads, Body 8x6mm"
  rrect5% 2.2x3.6 smd: 1(-5.1,0) 2(5.1,0)
  silkscreen extent -4.3,-3.3 4.3,3.3, body extent -5.95,-3.25 5.95,3.25, height 2.5
EQ33 [mm]
  round 1.5 hole 1: 1(11.25,25.5) 2(7.75,25.5) 3(4.25,25.5) 4(0.75,25.5) 5(-2.75,25.5)
  silkscreen extent -17.75,-21.98 17.75,26.65, body extent -17.85,-21.9 17.75,26.5, height 13.5
FCC_disclaimer [mm]
FP-B57371V2474J060_0603-MFG [mm]
  rrect10% 1x1 smd paste+0 mask+0: 1(-1,0) 2(1,0)
  silkscreen extent -0.13,-0.47 0.13,0.47, body extent -0.8,-0.4 0.8,0.4, height 0.9
FP-MP6924AGS-P_SOIC8-MFG [mm]
  rrect16% 1.6x0.61 smd paste+0 mask+0: 1(-2.7,1.905) 2(-2.7,0.635) 3(-2.7,-0.635) 4(-2.7,-1.905) 5(2.7,-1.905) 6(2.7,-0.635) 7(2.7,0.635) 8(2.7,1.905)
  silkscreen extent -4.17,-2.5 1.5,2.5, body extent -3,-2.45 3,2.45, height 1.75
FP-TLP383(GR-TPL,E_SO6-4-MFG [mm]
  rrect13% 1.3x0.8 smd paste+0 mask+0: 1(-4.75,1.27) 3(-4.75,-1.27) 4(4.75,-1.27) 6(4.75,1.27)
  silkscreen extent -3.7,-2.02 3.7,2.02, body extent -5.01,-1.92 5.01,1.92, height 2.3
FUSE_392 [mm] "LITTELFUSE"
  round 1.7 hole 1.05: 1(-2.54,0) 2(2.54,0)
  silkscreen extent -4.32,-2.03 4.32,2.03, body extent -4.25,-2 4.25,2, height 8
GBL610 [mm]
  oval 2.4x1.6 / inner oval 2.4x1.2 / far side oval 2.5x1.7 hole 0.9 slot 1.8 at 0 deg mask+0.03: 1(-7.5,-2.4) 2(-2.5,-2.4) 3(2.5,-2.4) 4(7.5,-2.4)
  silkscreen extent -10.3,-3.55 10.3,-0.05, body extent -10.3,-3.6 10.3,-0.1, height 13.5
Keystone5011#1 [mil] "Keystone Multipurpose loops"
  round 87 hole 63: 1(0,0)
  silkscreen extent -70,-70 70,70, body extent -63,-63 63,62, height 319
Keystone5011#2 [mil] "Keystone Multipurpose loops"
  round 86.61 hole 55.12: 1(0,0)
  silkscreen extent -51,-51 51,51
Keystone5011#3 [mil] "Keystone Multipurpose loops"
  round 59.06 hole 31.5: 1(0,0)
  silkscreen extent -35,-35 35,35
L_Ring_H_D=16.76mm [mil]
  round 60 hole 30: 1(-254.92,0) 2(254.92,0)
  silkscreen extent -330,-330 330,330
Littelfuse_V275LA_7MM [mm] "TH, 2-Leads, Dia 9mm"
  round 1.45 hole 0.95: 1(-2.5,-1.25) 2(2.5,1.25)
  silkscreen extent -4.5,-2.8 4.5,2.8, body extent -4.5,-2.8 4.49,2.8, height 10.5
PG-TDSON-8 [mm] "Infineon recommended land pattern"
  rect 1.2x0.65 smd: 1(-2.825,1.905) 2(-2.825,0.635) 3(-2.825,-0.635) 4(-2.825,-1.905)
  rect 0.5x0.7 smd: 5(3.175,-2) 6(3.175,-0.675) 7(3.175,0.675) 8(3.175,2)
  rect 4.5x4.7 smd paste-2.25: 9(0.675,0)
  silkscreen extent -3.74,-3 3.74,3, body extent -3.18,-2.89 3.18,2.9, height 1.1
PHE426_1300x400x900 [mm] "TH, 2-Leads, Body 13x4mm, Lead Spacing 10mm"
  round 1.35 hole 0.85: 1(-5,0) 2(5,0)
  silkscreen extent -6.5,-2 6.5,2, body extent -6.5,-2 6.5,2, height 9
REQ0038A-MFG [mm]
  rrect20% 0.7x0.5 smd paste-1000 mask+0: 1(-2.5,3.625) 15(-2.5,-3.625) 20(2.5,-3.625) 34(2.5,3.625)
  rrect40% 0.7x0.25 smd paste+0 mask+0: 2(-2.5,3) 3(-2.5,2.5) 4(-2.5,2) 5(-2.5,1.5) 6(-2.5,1) 7(-2.5,0.5) 8(-2.5,0) 9(-2.5,-0.5) 10(-2.5,-1) 11(-2.5,-1.5) 12(-2.5,-2) 13(-2.5,-2.5) 14(-2.5,-3) 21(2.5,-3) 22(2.5,-2.5) 23(2.5,-2) 24(2.5,-1.5) 25(2.5,-1) 26(2.5,-0.5) 27(2.5,0) 28(2.5,0.5) 29(2.5,1) 30(2.5,1.5) 31(2.5,2) 32(2.5,2.5) 33(2.5,3)
  rrect40% 0.25x0.7 smd paste+0 mask+0: 16(0.275,-3.85) 17(0.775,-3.85) 18(1.275,-3.85) 19(1.775,-3.85) 35(1.775,3.85) 36(1.275,3.85) 37(0.775,3.85) 38(0.275,3.85)
  rrect5% 2.1x6.6 smd paste-1000 mask+0: 39(0.9,0)
  silkscreen extent -3.62,-4.05 -0.23,4.05, body extent -2.65,-4 2.65,4, height 1
Rubycon_630x1100 [mm] "TH, 2-Leads, Dia 6.3mm, Lead Spacing 2.5mm"
  rrect50% 1.125x1.125 hole 0.75: 1(-1.25,0)
  round 1.125 hole 0.75: 2(1.25,0)
  silkscreen extent -3.4,-3.4 3.41,3.4, body extent -3.4,-3.4 3.41,3.4, height 12.51
SMB [mm] "Molded Diode, 2-Leads, Body 5.4x3.6mm, IPC Medium Density, based on OnSemi component dimensions"
  rect 2.159x2.743 smd: 1(-2.21,0) 2(2.21,0)
  silkscreen extent -3.94,-2.08 3.18,2.08, body extent -2.7,-1.8 2.7,1.8, height 2.32
SOD-123 [mm] "On Semi recommended land pattern"
  rect 0.915x1.22 smd: 1(-1.638,0) 2(1.638,0)
  silkscreen extent -2.74,-1.17 2.03,1.17, body extent -1.93,-0.9 1.93,0.9, height 1.35
SOD-123FL [mm] "Copied from SOD-123"
  rect 0.915x1.22 smd: 1(-1.637,0) 2(1.637,0)
  silkscreen extent -2.74,-1.16 1.68,1.16, body extent -1.9,-0.9 1.9,0.9, height 1
SOD-323 [mm] "NXP recommended land pattern"
  rect 0.6x0.6 smd paste-0.05: 1(-1.1,0) 2(1.1,0)
  silkscreen extent -2.06,-0.86 1.52,0.86, body extent -1.3,-0.67 1.3,0.68, height 1.1
SOT-23 [mm] "SOT23, 3-Leads, Body 2.9x1.3mm, Pitch 0.95mm, Lead Span 2.5mm, IPC Medium Density"
  rrect50% 1x0.6 smd: 1(-1.2,0.95) 2(-1.2,-0.95) 3(1.2,0)
  silkscreen extent -1.63,-1.5 0.7,1.5, body extent -1.16,-1.45 1.21,1.45, height 1
T10x6x5 [mm]
  round 2.5 hole 1.6: 1(3.525,3.525) 2(3.525,-3.475) 3(-3.475,-3.475) 4(-3.475,3.525)
  silkscreen extent -3.98,-7.97 4.02,8.03, body extent -3.97,-7.97 4.03,8.03, height 9
TI_Stacked_Overlay_Small [mm]
  silkscreen extent -10.63,-2.49 10.63,2.49
TO-220AB [mm] "Copied from Altium's version of TO3B"
  rrect25% 1.8x3 hole 1.27: 1(-2.54,0)
  oval 1.8x3 hole 1.27: 2(0,0) 3(2.54,0)
  silkscreen extent -5.61,-1.49 5.61,3.2, body extent -5.61,-1.49 5.61,3.2, height 19.42
WCAP-FTX2_1500x700x1250 [mm] "TH, 2-Leads, Body 15x7mm, Pin Spacing 12.5mm"
  round 1.4 hole 0.9: 1(-6.25,0) 2(6.25,0)
  silkscreen extent -7.5,-3.6 7.5,3.6, body extent -7.5,-3.5 7.5,3.5, height 12.3
WEEE_Minimum [mm] "WEEElie bin"
  silkscreen extent -2.42,-4.38 2.52,2.65

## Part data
BD1 BD2: library part BD
C1 C2: library part CMP-0012312-3, "CAP, Film, 0.22 uF, 275 V, +/- 10%, TH", Cap_Case=15x7x12.5, Manufacturer="Wurth Elektronik", Supplier Part Number 1=732-5888-ND, Tolerance_%=10%, Value1=Unknown, Value2=275V, ValueDisplayed=0.22uF
C3 C5: library part CMP-0006607-2, "CAP, CERM, 0.1 uF, 25 V, +/- 10%, X5R, 0402", Cap_Case=0402, Manufacturer=MuRata, Supplier Part Number 1=490-5920-1-ND, TempCo=X5R, Tolerance_%=10%, Value1=Unknown, Value2=25V, ValueDisplayed=0.1uF
C4 C112: library part CMP-0080807-1, "CAP, AL, 100 µF, 35 V, +/- 20%, TH", Cap_Case=6.3x11, Manufacturer=Rubycon, Supplier Part Number 1=1189-2268-ND, Tolerance_%=20%, Value2=35V, ValueDisplayed=100µF
C9: library part CMP-0080610-1, "CAP, CERM, 0.1 µF, 25 V,+/- 10%, X7R, AEC-Q200 Grade 1, 0402", Cap_Case=0402, Manufacturer=TDK, Supplier Part Number 1=445-6902-1-ND, TempCo=X7R, Tolerance_%=10%, Value2=25V, ValueDisplayed=0.1µF
C21 C23 C117 C128: library part CMP-0079720-1, "CAP, CERM, 1 µF, 25 V,+/- 10%, X7R, 0603", Cap_Case=0603, Manufacturer=MuRata, Supplier Part Number 1=490-10888-1-ND, TempCo=X7R, Tolerance_%=10%, Value2=25V, ValueDisplayed=1µF
C22 C24 C102 C111: library part CMP-0007071-4, "CAP, CERM, 22 pF, 50 V, +/- 5%, C0G/NP0, AEC-Q200 Grade 1, 0603", Cap_Case=0603, Manufacturer=TDK, Supplier Part Number 1=445-5632-1-ND, TempCo=C0G/NP0, Tolerance_%=5%, Value1=Unknown, Value2=50V, ValueDisplayed=22pF
C25 C27: library part C_film, Alternate Manufacturer=-, Manufacturer="Used in BOM report"
C28: library part CMP-0009029-2, "CAP, CERM, 10 pF, 1000 V, +/- 5%, C0G/NP0, 1206", Cap_Case=1206, Manufacturer=Vishay-Vitramon, Supplier Part Number 1=720-1010-1-ND, TempCo=C0G/NP0, Tolerance_%=5%, Value1=Unknown, Value2=1000V, ValueDisplayed=10pF
C29 C30: library part E-Cap, Alternate Manufacturer=-, Manufacturer="Used in BOM report"
C31: library part CMP-0008728-1, "CAP, CERM, 0.1 uF, 450 V, +/- 10%, X7T, 1206", Cap_Case=1206, Manufacturer=TDK, Supplier Part Number 1=445-8897-1-ND, TempCo=X7T, Tolerance_%=10%, Value1=Unknown, Value2=450V, ValueDisplayed=0.1uF
C32: library part CMP-0007210-1, "CAP, CERM, 3300 pF, 50 V, +/- 5%, C0G/NP0, 0603", Cap_Case=0603, Manufacturer=MuRata, Supplier Part Number 1=GRM1885C1H332JA01D-ND, TempCo=C0G/NP0, Tolerance_%=5%, Value1=Unknown, Value2=50V, ValueDisplayed=3300pF
C33: library part CMP-0007197-4, "CAP, CERM, 220 pF, 50 V, +/- 5%, C0G/NP0, 0603", Cap_Case=0603, Manufacturer=MuRata, Supplier Part Number 1=490-1435-1-ND, TempCo=C0G/NP0, Tolerance_%=5%, Value1=Unknown, Value2=50V, ValueDisplayed=220pF
C36: library part CMP-0007145-3, "CAP, CERM, 0.22 uF, 50 V, +/- 10%, X7R, AEC-Q200 Grade 1, 0603", Cap_Case=0603, Manufacturer=MuRata, Supplier Part Number 1=490-5402-1-ND, TempCo=X7R, Tolerance_%=10%, Value1=Unknown, Value2=50V, ValueDisplayed=0.22uF
C37 C39: library part CMP-0006754-4, "CAP, CERM, 1 uF, 25 V, +/- 10%, X7R, 0603", Cap_Case=0603, Manufacturer=AVX, Supplier Part Number 1=478-10046-1-ND, TempCo=X7R, Tolerance_%=10%, Value1=Unknown, Value2=25V, ValueDisplayed=1uF
C38: library part CMP-0007451-3, "CAP, CERM, 0.033 uF, 50 V, +/- 10%, X7R, 0603", Cap_Case=0603, Manufacturer=MuRata, Supplier Part Number 1=490-3286-1-ND, TempCo=X7R, Tolerance_%=10%, Value1=Unknown, Value2=50V, ValueDisplayed=0.033uF
C40: library part CMP-0006932-4, "CAP, CERM, 390 pF, 50 V, +/- 5%, C0G/NP0, 0603", Cap_Case=0603, Manufacturer=Kemet, Supplier Part Number 1=399-1069-1-ND, TempCo=C0G/NP0, Tolerance_%=5%, Value1=Unknown, Value2=50V, ValueDisplayed=390pF
C41: library part CMP-0006898-4, "CAP, CERM, 2200 pF, 50 V, +/- 10%, X7R, 0603", Cap_Case=0603, Manufacturer=Kemet, Supplier Part Number 1=399-1085-1-ND, TempCo=X7R, Tolerance_%=10%, Value1=Unknown, Value2=50V, ValueDisplayed=2200pF
C101 C110: library part CMP-0079095-1, "CAP, CERM, 0.1 µF, 50 V,+/- 10%, X7R, AEC-Q200 Grade 1, 0603", Cap_Case=0603, Manufacturer=AVX, Supplier Part Number 1=478-3540-1-ND, TempCo=X7R, Tolerance_%=10%, Value2=50V, ValueDisplayed=0.1µF
C103 C109: library part CMP-0012541-3, "CAP, Film, 0.015 uF, 630 V, +/- 20%, TH", Cap_Case=13x4x9mm, Manufacturer=Kemet, Supplier Part Number 1=399-11726-ND, Tolerance_%=20%, Value1=Unknown, Value2=630V, ValueDisplayed=0.015uF
C104 C105 C106 C107: library part E-Cap, "227AVG035MFBJ", Alternate Manufacturer=-, Manufacturer="Used in BOM report"
C108: library part CMP-0008885-2, "CAP, CERM, 150 pF, 630 V, +/- 5%, C0G/NP0, 1206", Cap_Case=1206, Manufacturer=MuRata, Supplier Part Number 1=490-5274-1-ND, TempCo=C0G/NP0, Tolerance_%=5%, Value1=Unknown, Value2=630V, ValueDisplayed=150pF
C113: library part CMP-0006943-4, "CAP, CERM, 4700 pF, 50 V, +/- 10%, X7R, 0603", Cap_Case=0603, Manufacturer=Kemet, Supplier Part Number 1=399-1087-1-ND, TempCo=X7R, Tolerance_%=10%, Value1=Unknown, Value2=50V, ValueDisplayed=4700pF
C114: library part CMP-0007498-4, "CAP, CERM, 4.7 uF, 10 V, +/- 20%, X7R, 0603", Cap_Case=0603, Manufacturer=MuRata, TempCo=X7R, Tolerance_%=20%, Value1=Unknown, Value2=10V, ValueDisplayed=4.7uF
C115: library part CMP-0007052-4, "CAP, CERM, 1 uF, 35 V, +/- 10%, X7R, 0603", Cap_Case=0603, Manufacturer=TDK, Supplier Part Number 1=445-7414-1-ND, TempCo=X7R, Tolerance_%=10%, Value1=Unknown, Value2=35V, ValueDisplayed=1uF
C116: library part CMP-0081060-1, "CAP, CERM, 3300 pF, 50 V,+/- 1%, C0G/NP0, 0603", Cap_Case=0603, Manufacturer=Kemet, Supplier Part Number 1=399-11151-1-ND, TempCo=C0G/NP0, Tolerance_%=1%, Value2=50V, ValueDisplayed=3300pF
C118: library part CMP-0007191-4, "CAP, CERM, 180 pF, 50 V, +/- 5%, C0G/NP0, 0603", Cap_Case=0603, Manufacturer=MuRata, Supplier Part Number 1=490-1433-1-ND, TempCo=C0G/NP0, Tolerance_%=5%, Value1=Unknown, Value2=50V, ValueDisplayed=180pF
C119: library part CMP-0007049-4, "CAP, CERM, 0.047 uF, 50 V, +/- 10%, X7R, 0603", Cap_Case=0603, Manufacturer=TDK, Supplier Part Number 1=445-1313-1-ND, TempCo=X7R, Tolerance_%=10%, Value1="0.049007 ohm", Value2=50V, ValueDisplayed=0.047uF
C120: library part CMP-0006954-4, "CAP, CERM, 560 pF, 50 V, +/- 10%, X7R, 0603", Cap_Case=0603, Manufacturer=Kemet, Supplier Part Number 1=399-1076-1-ND, TempCo=X7R, Tolerance_%=10%, Value1=Unknown, Value2=50V, ValueDisplayed=560pF
C121: library part CMP-0080091-1, "CAP, CERM, 100 pF, 50 V,+/- 1%, C0G/NP0, 0603", Cap_Case=0603, Manufacturer=Kemet, Supplier Part Number 1=399-7819-1-ND, TempCo=C0G/NP0, Tolerance_%=1%, Value2=50V, ValueDisplayed=100pF
C122 C123: library part CMP-0084048-1, "CAP, CERM, 0.022 µF, 1000 V,+/- 10%, X7R, AEC-Q200 Grade 1, 1206", Cap_Case=1206, Manufacturer=Kemet, TempCo=X7R, Tolerance_%=10%, Value2=1000V, ValueDisplayed=0.022µF
C124: library part CMP-0006861-4, "CAP, CERM, 0.1 uF, 50 V, +/- 10%, X7R, 0603", Cap_Case=0603, Manufacturer=Kemet, Supplier Part Number 1=399-5089-1-ND, TempCo=X7R, Tolerance_%=10%, Value1=Unknown, Value2=50V, ValueDisplayed=0.1uF
C125 C126: library part CMP-0006992-4, "CAP, CERM, 100 pF, 100 V, +/- 1%, C0G/NP0, 0603", Cap_Case=0603, Manufacturer=TDK, Supplier Part Number 1=445-5378-1-ND, TempCo=C0G/NP0, Tolerance_%=1%, Value1=Unknown, Value2=100V, ValueDisplayed=100pF
C127: library part CMP-0006976-5, "CAP, CERM, 1000 pF, 50 V, +/- 10%, X7R, 0603", Cap_Case=0603, Manufacturer=Kemet, Supplier Part Number 1=399-5348-1-ND, TempCo=X7R, Tolerance_%=10%, Value1=Unknown, Value2=50V, ValueDisplayed=1000pF
CY1 CY2 CY101: library part CMP-0077997-1, "CAP, CERM, 1000 pF, X1 440 VAC/Y1 250 VAC, +/- 20%, E, 8x6mm", Cap_Case=8x6mm, Manufacturer=MuRata, TempCo=E, Tolerance_%=20%, ValueDisplayed=1000pF
D1: library part CMP-0028466-3, "Diode, Schottky, 35 V, 0.1 A, 0603 Diode", Manufacturer=Bourns, Value1=0.1A, Value2=0.44V
D2 D3: library part CMP-0029032-2, "Diode, GP, 1KV, 1 A, SOD-123F", Manufacturer="ON Semiconductor", Supplier Part Number 1=ES1JFLDKR-ND, Value1=1A, Value2=1V
D4: library part CMP-0005831-4, "Diode, Zener, 12 V, 200 mW, SOD-323", Manufacturer="Diodes Inc.", Power_W=200mW, Value1=0.2W
D21 D25: library part CMP-0077014-1, "Diode, GP, 1000V, 3 A, SMB", Manufacturer="Diodes Incorporated", Supplier Part Number 1=497-3771-1-ND, Value1=3A, Value2=1.3V
D22: library part CMP-0085337-1, "Diode, Ultrafast, 600 V, 8 A, TO-220AB", Manufacturer="ON Semiconductor", Value1=8A, Value2=16V
D23 D24: library part CMP-0079597-2, "Diode, Switching, 75 V, 0.15 A, AEC-Q101, SOD-323", Manufacturer="Diodes Inc.", Value1=0.15A, Value2=1.25V
D101: library part CMP-0076928-2, "Diode, Schottky, 40 V, 0.35 A, SOD-323", Manufacturer="Micro Commercial Components", Value1=0.35A, Value2=0.6V
D102: library part CMP-0029148-2, "Diode, Ultrafast, 600 V, 1 A, SOD-123FL", Manufacturer="Micro Commercial Components", Value1=1A, Value2=1.7V
D103: library part CMP-0085766-1, "Diode, Zener, 18 V, 300 mW, SOD-323", Manufacturer="ON Semiconductor", Power_W=300mW, Value1=0.3W
F1: library part CMP-0003561-2, "Fuse, 3.15 A, 250VAC/VDC, TH", Irating_A=3.15A, Manufacturer=Littelfuse, Supplier Part Number 1=F5504CT-ND
L1 L2 L102: library part CM_Choke_Planar, Alternate Manufacturer=-, Manufacturer="Used in BOM report"
L21: library part "L_FIX_more pins", Alternate Manufacturer=-, Manufacturer="Used in BOM report"
L22 L101: library part L_FIX, Alternate Manufacturer=-, Manufacturer="Used in BOM report"
Logo1: library part CMP-0074844-1
Logo2: library part CMP-0074838-1, "Texas Instrument Corporate Signature"
Logo3: library part CMP-0074847-1, "FCC_disclaimer"
Logo4: library part CMP-0074769-1
Q1: library part CMP-0000387-2, "Transistor, NPN, 40 V, 0.2 A, SOT-23", Manufacturer="Diodes Inc.", Supplier Part Number 1=MMBT3904-FDICT-ND, Value1="0.2 A", Value2=400
Q2: library part CMP-0000090-3, "MOSFET, P-CH, -60 V, -1.6 A, SOT-23", Alternate Manufacturer=None, Manufacturer=Vishay-Siliconix, Value1=0.4, Value2="2.7 nC"
Q3 Q4: library part CMP-0000769-1, "MOSFET, N-CH, 60 V, 0.17 A, SOT-23", Alternate Manufacturer=None, Manufacturer="Diodes Inc.", Supplier Part Number 1=2N7002-FDICT-ND, Value1=7, Value2="223 nC"
Q101 Q102: library part CMP-0000296-1, "MOSFET, N-CH, 30 V, 100 A, PG-TDSON-8", Alternate Manufacturer=None, Manufacturer="Infineon Technologies", PartNumber="BSC020N03MS G", Supplier Part Number 1=BSC020N03MSGINCT-ND, Value1=0.002, Value2="45 nC"
Q103 Q104: library part CMP-0087394-2, "Optoisolator Transistor Output 5000Vrms 1 Channel 6-SO", Manufacturer=Toshiba
R1 R2: library part CMP-0018641-3, "RES, 2.2 k, 5%, 0.25 W, AEC-Q200 Grade 0, 1206", Manufacturer=Vishay-Dale, Power_W=250mW, Supplier Part Number 1=541-2.2KECT-ND, TempCo="200 ppm/C", Tolerance_%=5%, Value2=0.25W, Value_Code=2k20, ValueDisplayed=2.2k
R3: library part CMP-0025885-5, "RES, 0, 5%, 0.1 W, 0603", Manufacturer=Yageo, Power_W=100mW, Supplier Part Number 1=311-0.0GRCT-ND, TempCo="200 ppm/C", Tolerance_%=5%, Value2=0.1W, Value_Code=0000, ValueDisplayed=0
R4: library part CMP-0026631-1, "RES, 4.70 k, 1%, 0.063 W, 0402", Manufacturer="TE Connectivity", Power_W=63mW, Supplier Part Number 1=A121542CT-ND, TempCo="100 ppm/C", Tolerance_%=1%, Value2=0.063W, Value_Code=4k70, ValueDisplayed=4.70k
R5 R6 R7: library part CMP-0026401-2, "RES, 499 k, 1%, 0.063 W, AEC-Q200 Grade 0, 0402", Manufacturer=Vishay-Dale, Power_W=63mW, Supplier Part Number 1=541-499KLCT-ND, TempCo="100 ppm/C", Tolerance_%=1%, Value2=0.063W, Value_Code=499k
R21 R23 R28: library part CMP-0021137-3, "RES, 2.74 M, 1%, 0.125 W, AEC-Q200 Grade 0, 0805", Manufacturer=Vishay-Dale, Power_W=125mW, Supplier Part Number 1=541-2.74MCCT-ND, TempCo="100 ppm/C", Tolerance_%=1%, Value2=0.125W, Value_Code=2M74, ValueDisplayed=2.74M
R22 R26 R27: library part CMP-0021222-4, "RES, 3.24 M, 1%, 0.125 W, AEC-Q200 Grade 0, 0805", Manufacturer=Vishay-Dale, Power_W=125mW, Supplier Part Number 1=541-3.24MCCT-ND, TempCo="100 ppm/C", Tolerance_%=1%, Value2=0.125W, Value_Code=3M24, ValueDisplayed=3.24M
R24 R25 R101 R105: library part CMP-0025717-4, "RES, 150 k, 5%, 0.1 W, AEC-Q200 Grade 0, 0603", Manufacturer=Vishay-Dale, Power_W=100mW, Supplier Part Number 1=541-150KGCT-ND, TempCo="200 ppm/C", Tolerance_%=5%, Value2=0.1W, Value_Code=150k
R29: library part CMP-0022943-5, "RES, 24.3 k, 1%, 0.1 W, 0603", Manufacturer=Yageo, Power_W=100mW, Supplier Part Number 1=311-24.3KHRCT-ND, TempCo="100 ppm/C", Tolerance_%=1%, Value2=0.1W, Value_Code=24k3, ValueDisplayed=24.3k
R30: library part CMP-0021005-3, "RES, 1.82 M, 1%, 0.125 W, AEC-Q200 Grade 0, 0805", Manufacturer=Vishay-Dale, Power_W=125mW, Supplier Part Number 1=541-1.82MCCT-ND, TempCo="100 ppm/C", Tolerance_%=1%, Value2=0.125W, Value_Code=1M82, ValueDisplayed=1.82M
R31: library part CMP-0023229-5, "RES, 64.9, 1%, 0.1 W, 0603", Manufacturer=Yageo, Power_W=100mW, Supplier Part Number 1=311-64.9HRCT-ND, TempCo="100 ppm/C", Tolerance_%=1%, Value2=0.1W, Value_Code=64R9, ValueDisplayed=64.9
R32: library part CMP-0025754-1, "RES, 20, 5%, 0.1 W, 0603", Manufacturer=Vishay-Dale, Power_W=100mW, Supplier Part Number 1=541-20GCT-ND, TempCo="200 ppm/C", Tolerance_%=5%, Value2=0.1W, Value_Code=20R0, ValueDisplayed=20
R33: library part CMP-0025939-5, "RES, 750, 5%, 0.1 W, 0603", Manufacturer=Yageo, Power_W=100mW, Supplier Part Number 1=311-750GRCT-ND, TempCo="100 ppm/C", Tolerance_%=5%, Value2=0.1W, Value_Code=750R, ValueDisplayed=750
R34 R38: library part CMP-0025815-4, "RES, 47, 5%, 0.1 W, AEC-Q200 Grade 0, 0603", Manufacturer=Vishay-Dale, Power_W=100mW, Supplier Part Number 1=541-47GCT-ND, TempCo="200 ppm/C", Tolerance_%=5%, Value2=0.1W, Value_Code=47R0, ValueDisplayed=47
R35: library part CMP-0025725-2, "RES, 180 k, 5%, 0.1 W, 0603", Manufacturer=Vishay-Dale, Power_W=100mW, Supplier Part Number 1=541-180KGCT-ND, TempCo="200 ppm/C", Tolerance_%=5%, Value2=0.1W, Value_Code=180k
R36: library part CMP-0025755-4, "RES, 220 k, 5%, 0.1 W, AEC-Q200 Grade 0, 0603", Manufacturer=Vishay-Dale, Power_W=100mW, Supplier Part Number 1=541-220KGCT-ND, TempCo="200 ppm/C", Tolerance_%=5%, Value2=0.1W, Value_Code=220k
R37: library part CMP-0023232-5, "RES, 66.5 k, 1%, 0.1 W, 0603", Manufacturer=Yageo, Power_W=100mW, Supplier Part Number 1=311-66.5KHRCT-ND, TempCo="100 ppm/C", Tolerance_%=1%, Value2=0.1W, Value_Code=66k5, ValueDisplayed=66.5k
R102 R122: library part CMP-0017255-2, "RES, 0.003, 1%, 1 W, 1206", Manufacturer="Stackpole Electronics Inc", Power_W=1W, Supplier Part Number 1=CSNL1206FT3L00CT-ND, TempCo="50 ppm/C", Tolerance_%=1%, Value_Code=3L000, ValueDisplayed=0.003
R103: library part CMP-0022917-4, "RES, 220 k, 1%, 0.1 W, 0603", Manufacturer=Yageo, Power_W=100mW, Supplier Part Number 1=311-220KHRCT-ND, TempCo="100 ppm/C", Tolerance_%=1%, Value2=0.1W, Value_Code=220k
R104: library part CMP-0022951-5, "RES, 25.5 k, 1%, 0.1 W, 0603", Manufacturer=Yageo, Power_W=100mW, Supplier Part Number 1=311-25.5KHRCT-ND, TempCo="100 ppm/C", Tolerance_%=1%, Value2=0.1W, Value_Code=25k5, ValueDisplayed=25.5k
R106: library part CMP-0022900-4, "RES, 1.00, 1%, 0.1 W, 0603", Manufacturer=Yageo, Power_W=100mW, Supplier Part Number 1=311-1.00HRCT-ND, TempCo="200 ppm/C", Tolerance_%=1%, Value2=0.1W, Value_Code=1R00, ValueDisplayed=1.00
R107: library part CMP-0022913-5, "RES, 21.5 k, 1%, 0.1 W, 0603", Manufacturer=Yageo, Power_W=100mW, Supplier Part Number 1=311-21.5KHRCT-ND, TempCo="100 ppm/C", Tolerance_%=1%, Value2=0.1W, Value_Code=21k5, ValueDisplayed=21.5k
R108: library part CMP-0096703-1, "NTC Thermistor 470k 0603 (1608 Metric)", B Tolerance=3%, Digikey Part Number=495-B57371V2474J060CT-ND, Manufacturer=TDK, Mouser Part Number=871-B57371V2474J060, Operating Temperature Range="-55°C to +125°C", Power_W=180mW, Tolerance_%=5%
R109 R114 R115: library part CMP-0020707-3, "RES, 3.3 M, 5%, 0.125 W, AEC-Q200 Grade 0, 0805", Manufacturer=Panasonic, Power_W=125mW, Supplier Part Number 1=P3.3MACT-ND, TempCo="150 ppm/C", Tolerance_%=5%, Value2=0.125W, Value_Code=3M30, ValueDisplayed=3.3M
R110: library part CMP-0023050-5, "RES, 35.7 k, 1%, 0.1 W, 0603", Manufacturer=Yageo, Power_W=100mW, Supplier Part Number 1=311-35.7KHRCT-ND, TempCo="100 ppm/C", Tolerance_%=1%, Value2=0.1W, Value_Code=35k7, ValueDisplayed=35.7k
R111: library part CMP-0022804-5, "RES, 14.0 k, 1%, 0.1 W, 0603", Manufacturer=Yageo, Power_W=100mW, Supplier Part Number 1=311-14.0KHRCT-ND, TempCo="100 ppm/C", Tolerance_%=1%, Value2=0.1W, Value_Code=14k0, ValueDisplayed=14.0k
R112: library part CMP-0025886-5, "RES, 10 k, 5%, 0.1 W, 0603", Manufacturer=Yageo, Power_W=100mW, Supplier Part Number 1=311-10KGRCT-ND, TempCo="100 ppm/C", Tolerance_%=5%, Value2=0.1W, Value_Code=10k0, ValueDisplayed=10k
R113: library part CMP-0022051-5, "RES, 143, 1%, 0.1 W, AEC-Q200 Grade 0, 0603", Manufacturer=Vishay-Dale, Power_W=100mW, Supplier Part Number 1=541-143HCT-ND, TempCo="100 ppm/C", Tolerance_%=1%, Value2=0.1W, Value_Code=143R, ValueDisplayed=143
R116: library part CMP-0022588-5, "RES, 750, 1%, 0.1 W, AEC-Q200 Grade 0, 0603", Manufacturer=Vishay-Dale, Power_W=100mW, Supplier Part Number 1=541-750HCT-ND, TempCo="100 ppm/C", Tolerance_%=1%, Value2=0.1W, Value_Code=750R, ValueDisplayed=750
R117: library part CMP-0023142-5, "RES, 49.9 k, 1%, 0.1 W, 0603", Manufacturer=Yageo, Power_W=100mW, Supplier Part Number 1=311-49.9KHRCT-ND, TempCo="100 ppm/C", Tolerance_%=1%, Value2=0.1W, Value_Code=49k9, ValueDisplayed=49.9k
R118: library part CMP-0080488-1, "RES, 10.0 k, 1%, 0.1 W, 0603", Manufacturer="TT Electronics/IRC", Power_W=100mW, TempCo="100 ppm/C", Tolerance_%=1%, Value2=0.1W, Value_Code=10k0, ValueDisplayed=10.0k
R119: library part CMP-0023292-5, "RES, 82.0 k, 1%, 0.1 W, 0603", Manufacturer=Yageo, Power_W=100mW, Supplier Part Number 1=311-82.0KHRCT-ND, TempCo="100 ppm/C", Tolerance_%=1%, Value2=0.1W, Value_Code=82k0, ValueDisplayed=82.0k
R120: library part CMP-0023226-4, "RES, 649 k, 1%, 0.1 W, 0603", Manufacturer=Yageo, Power_W=100mW, Supplier Part Number 1=311-649KHRCT-ND, TempCo="100 ppm/C", Tolerance_%=1%, Value2=0.1W, Value_Code=649k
